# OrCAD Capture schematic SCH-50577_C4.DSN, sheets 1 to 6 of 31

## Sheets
1 31 Use Case Description: title: MIMXRT1180-EVK; rev: C4; company: NXP Semiconductors; note: SCH-50577, PDF: SPF-50577; note: 6501 William Cannon Drive West; note: Austin, TX 78735-8598
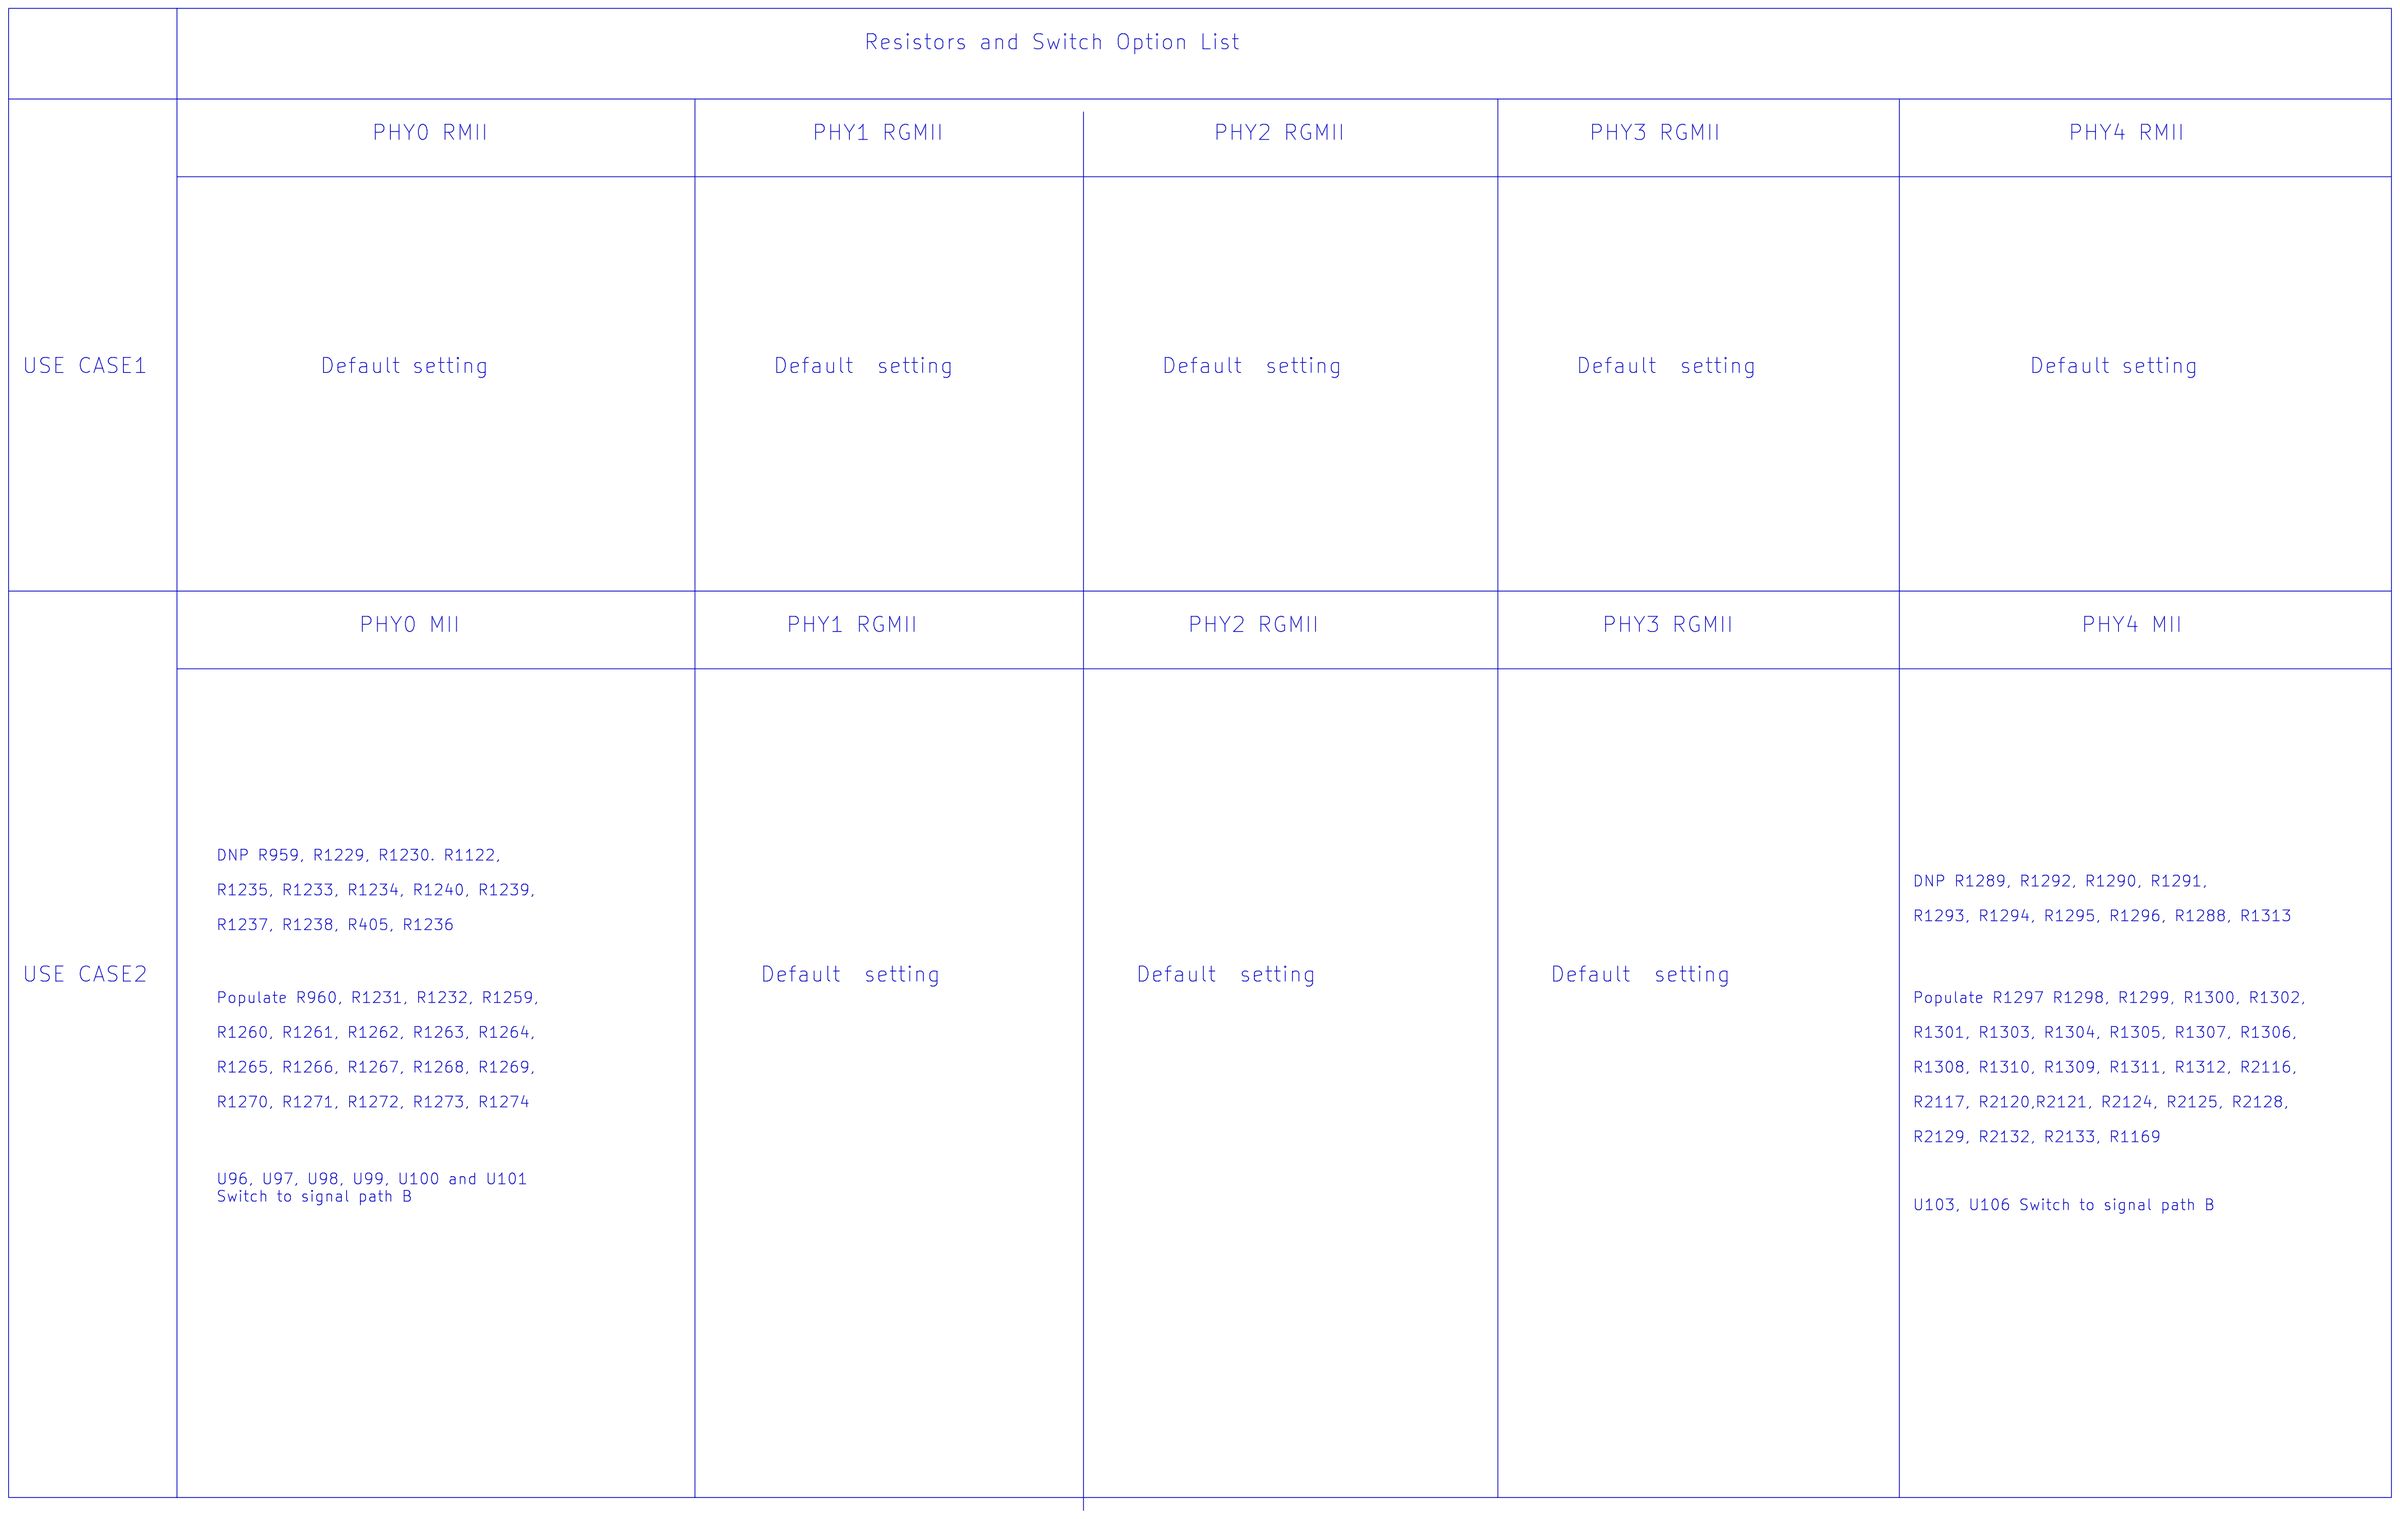
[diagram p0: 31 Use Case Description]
2 29 Serial to USB: size C
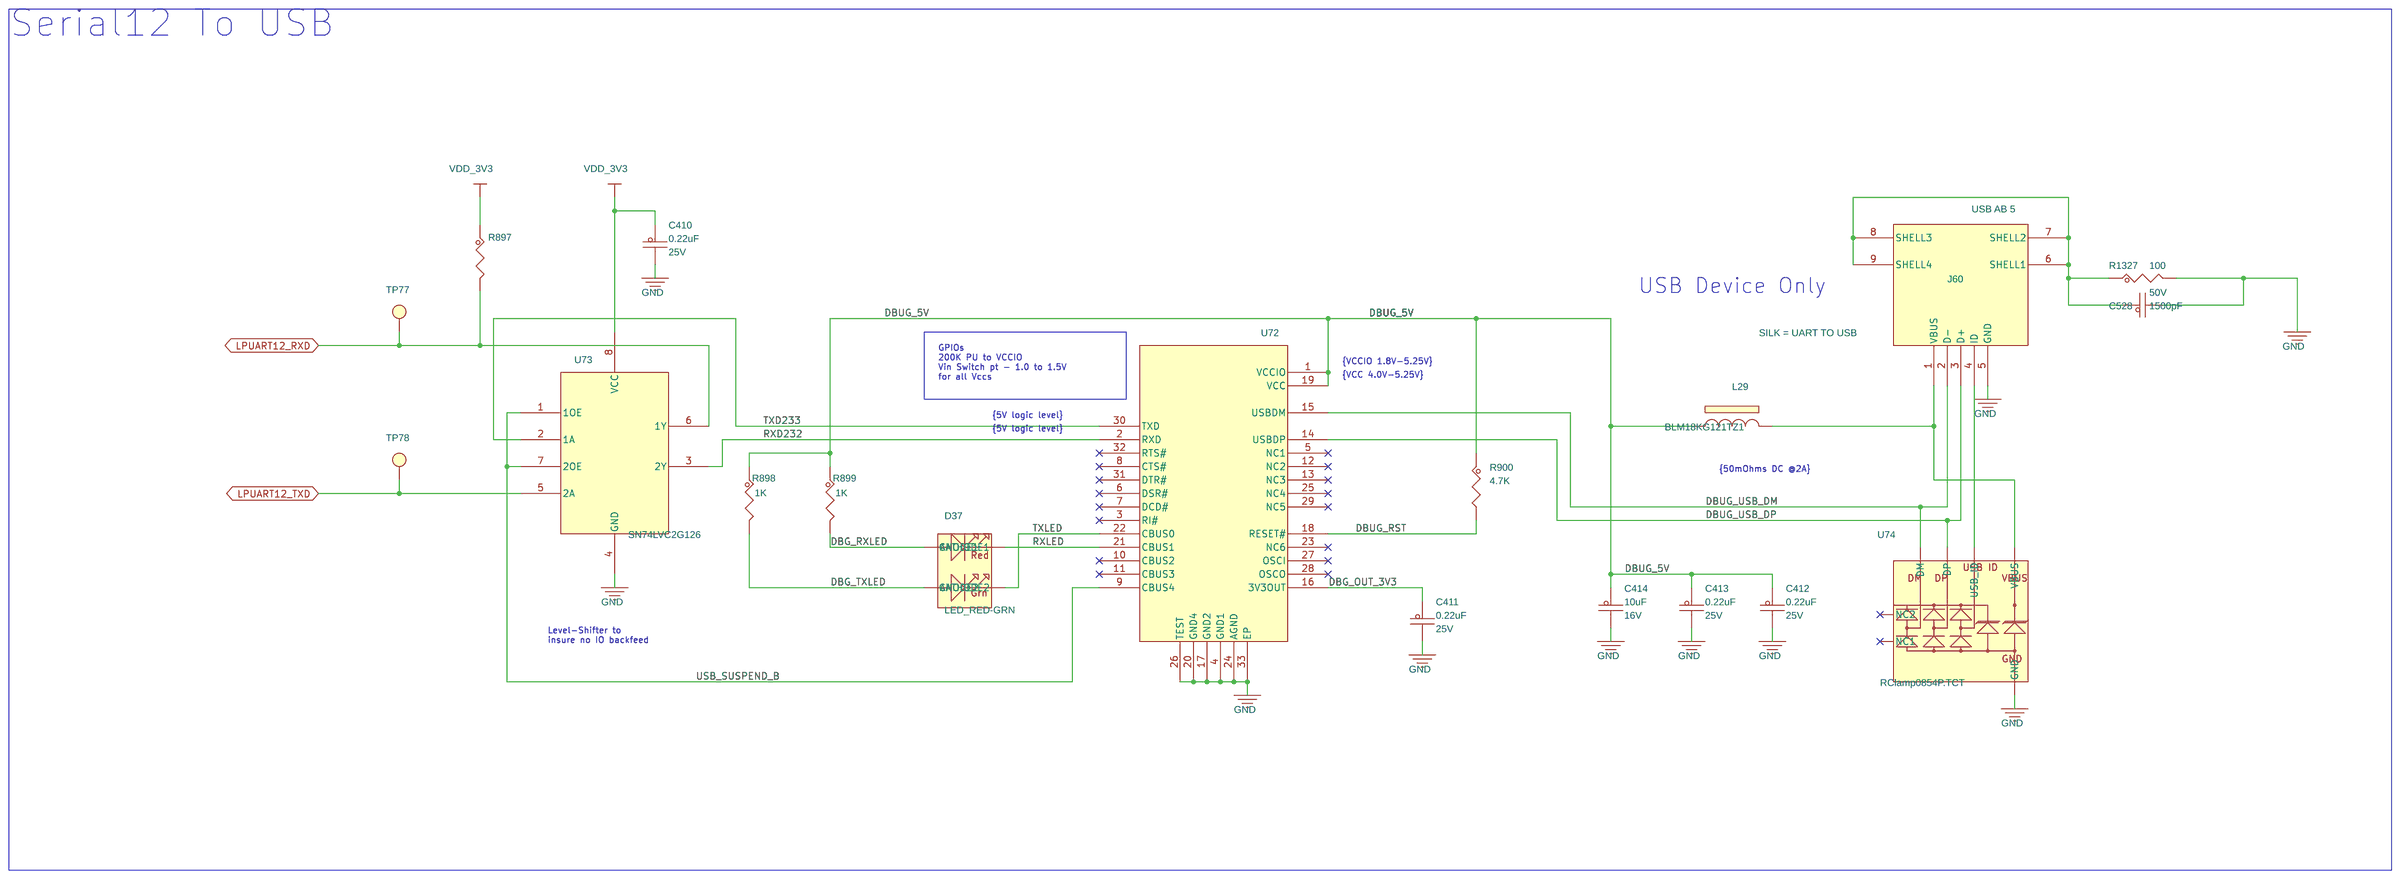
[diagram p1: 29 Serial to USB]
3 01 Cover
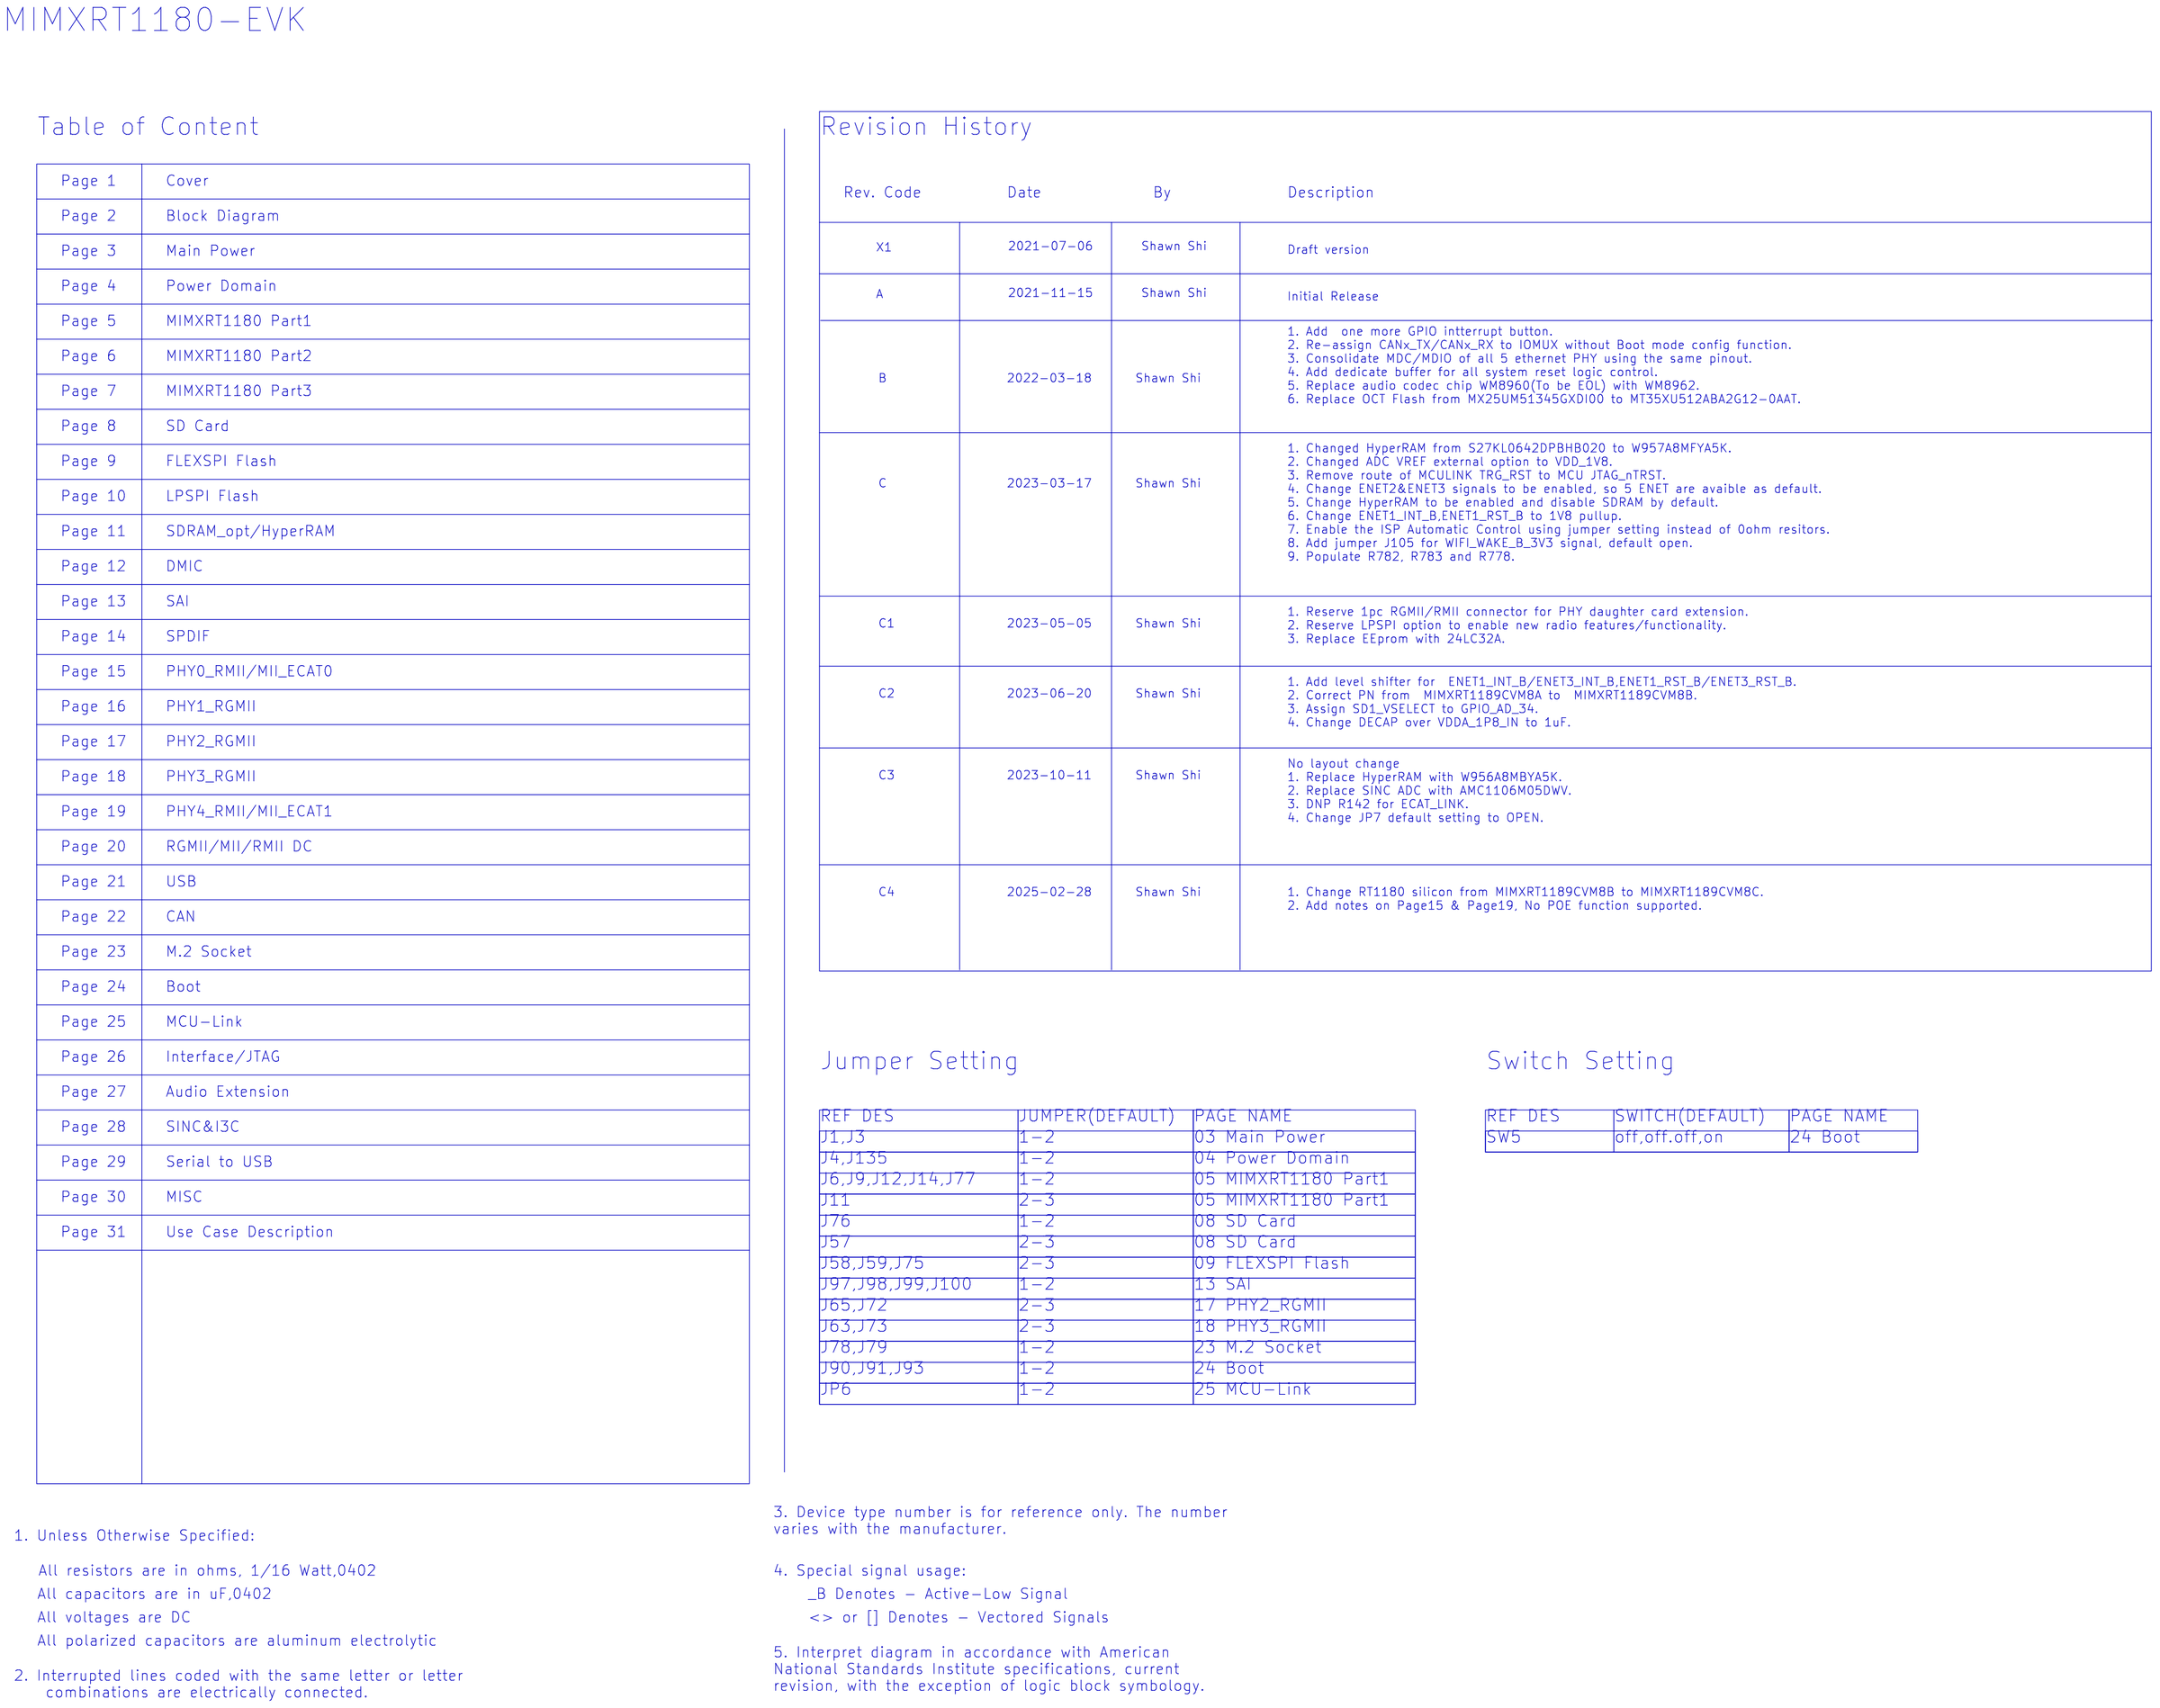
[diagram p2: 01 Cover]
4 02 Block Diagram
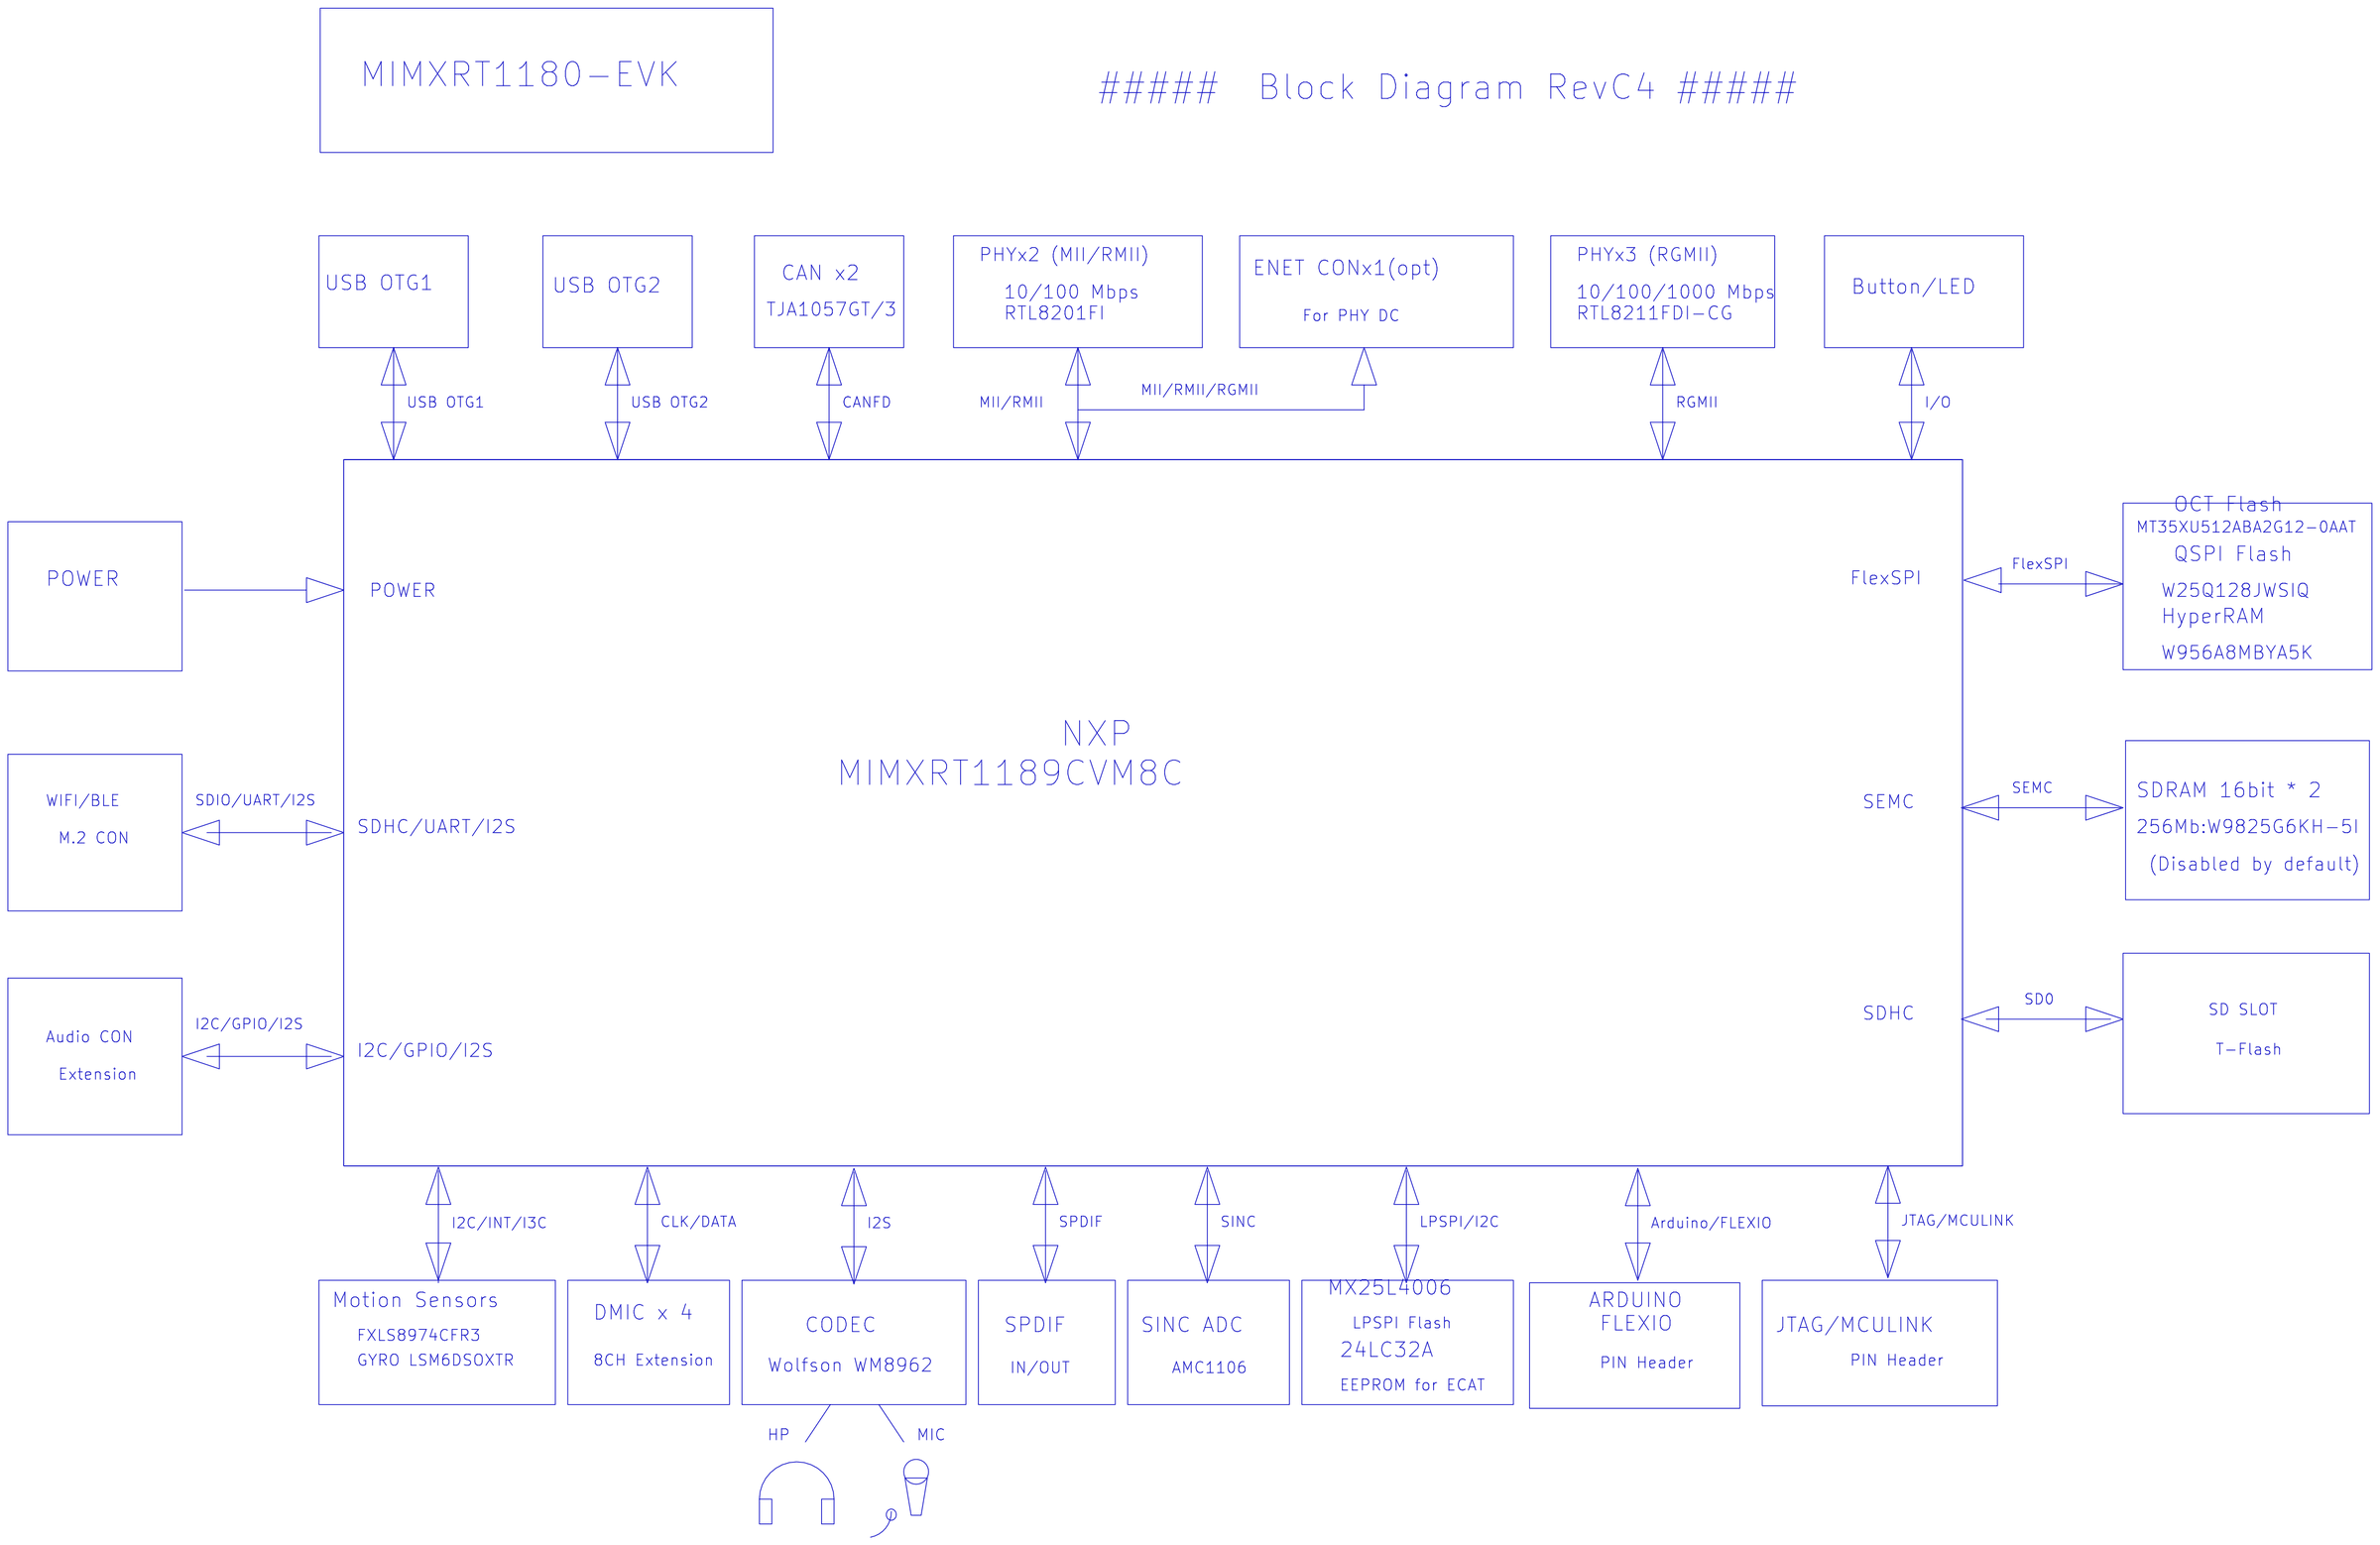
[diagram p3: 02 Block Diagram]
5 03 Main Power: size C
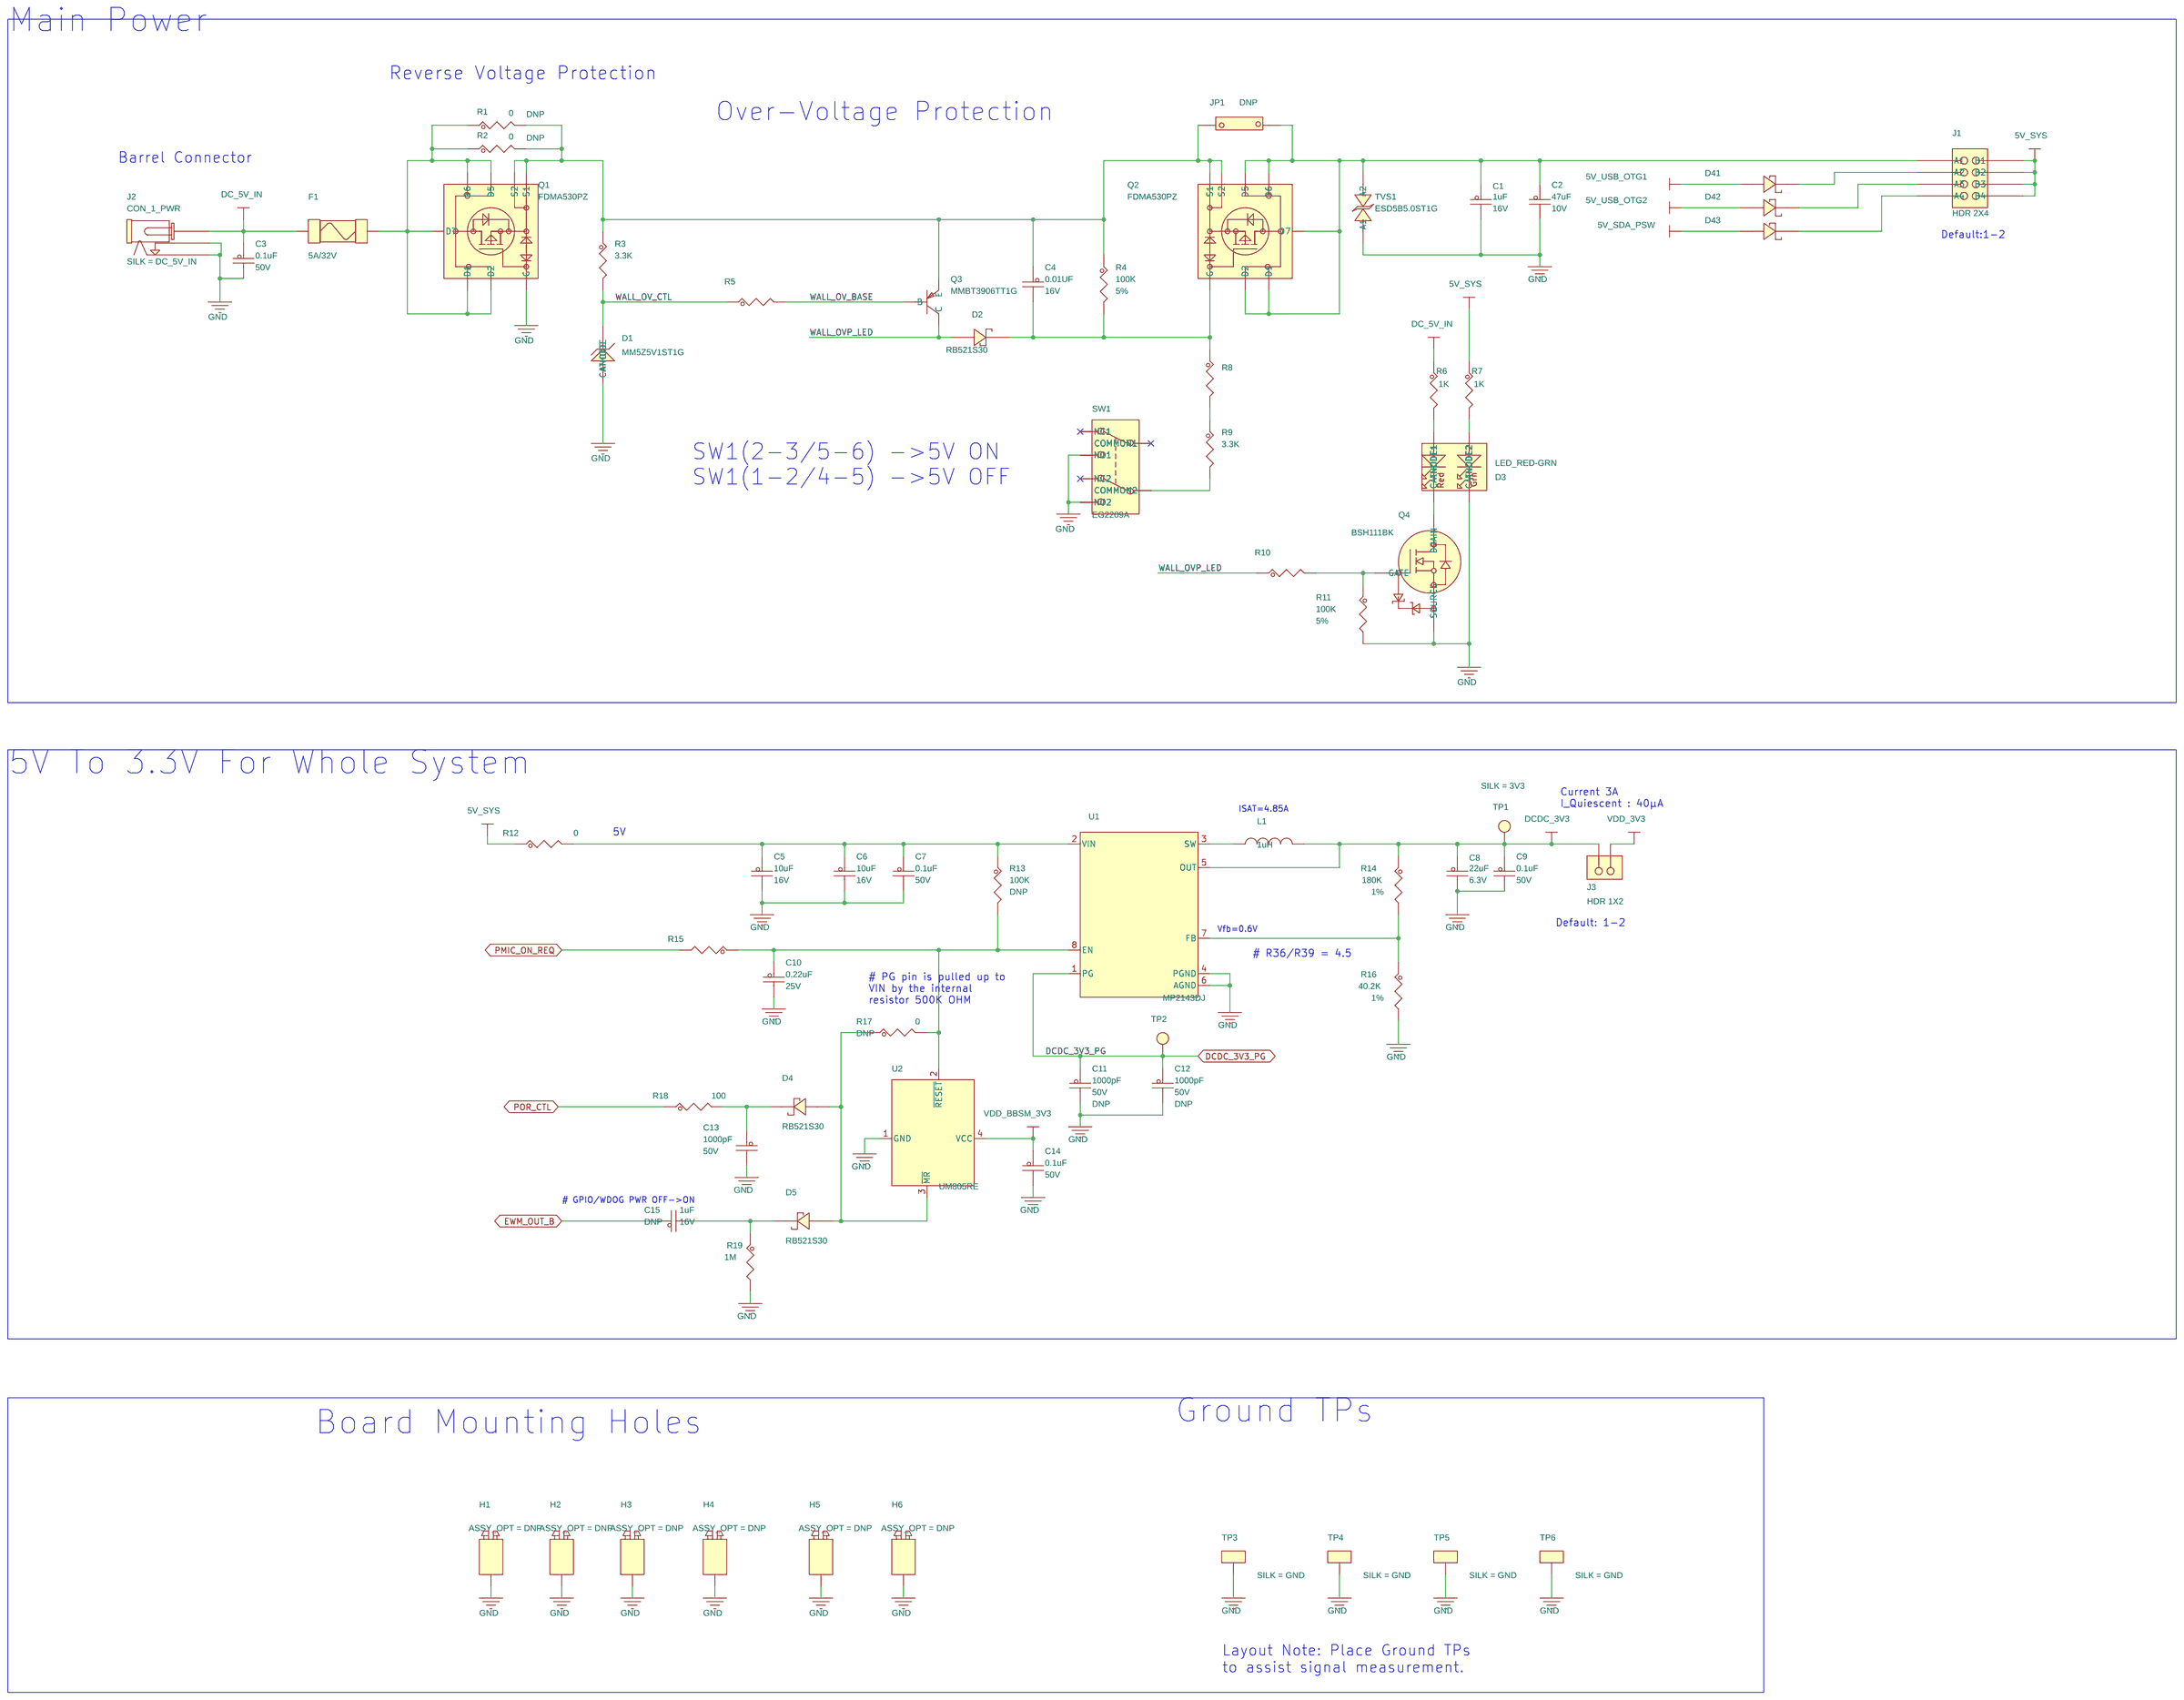
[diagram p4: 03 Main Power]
6 04 Power Domain: size C
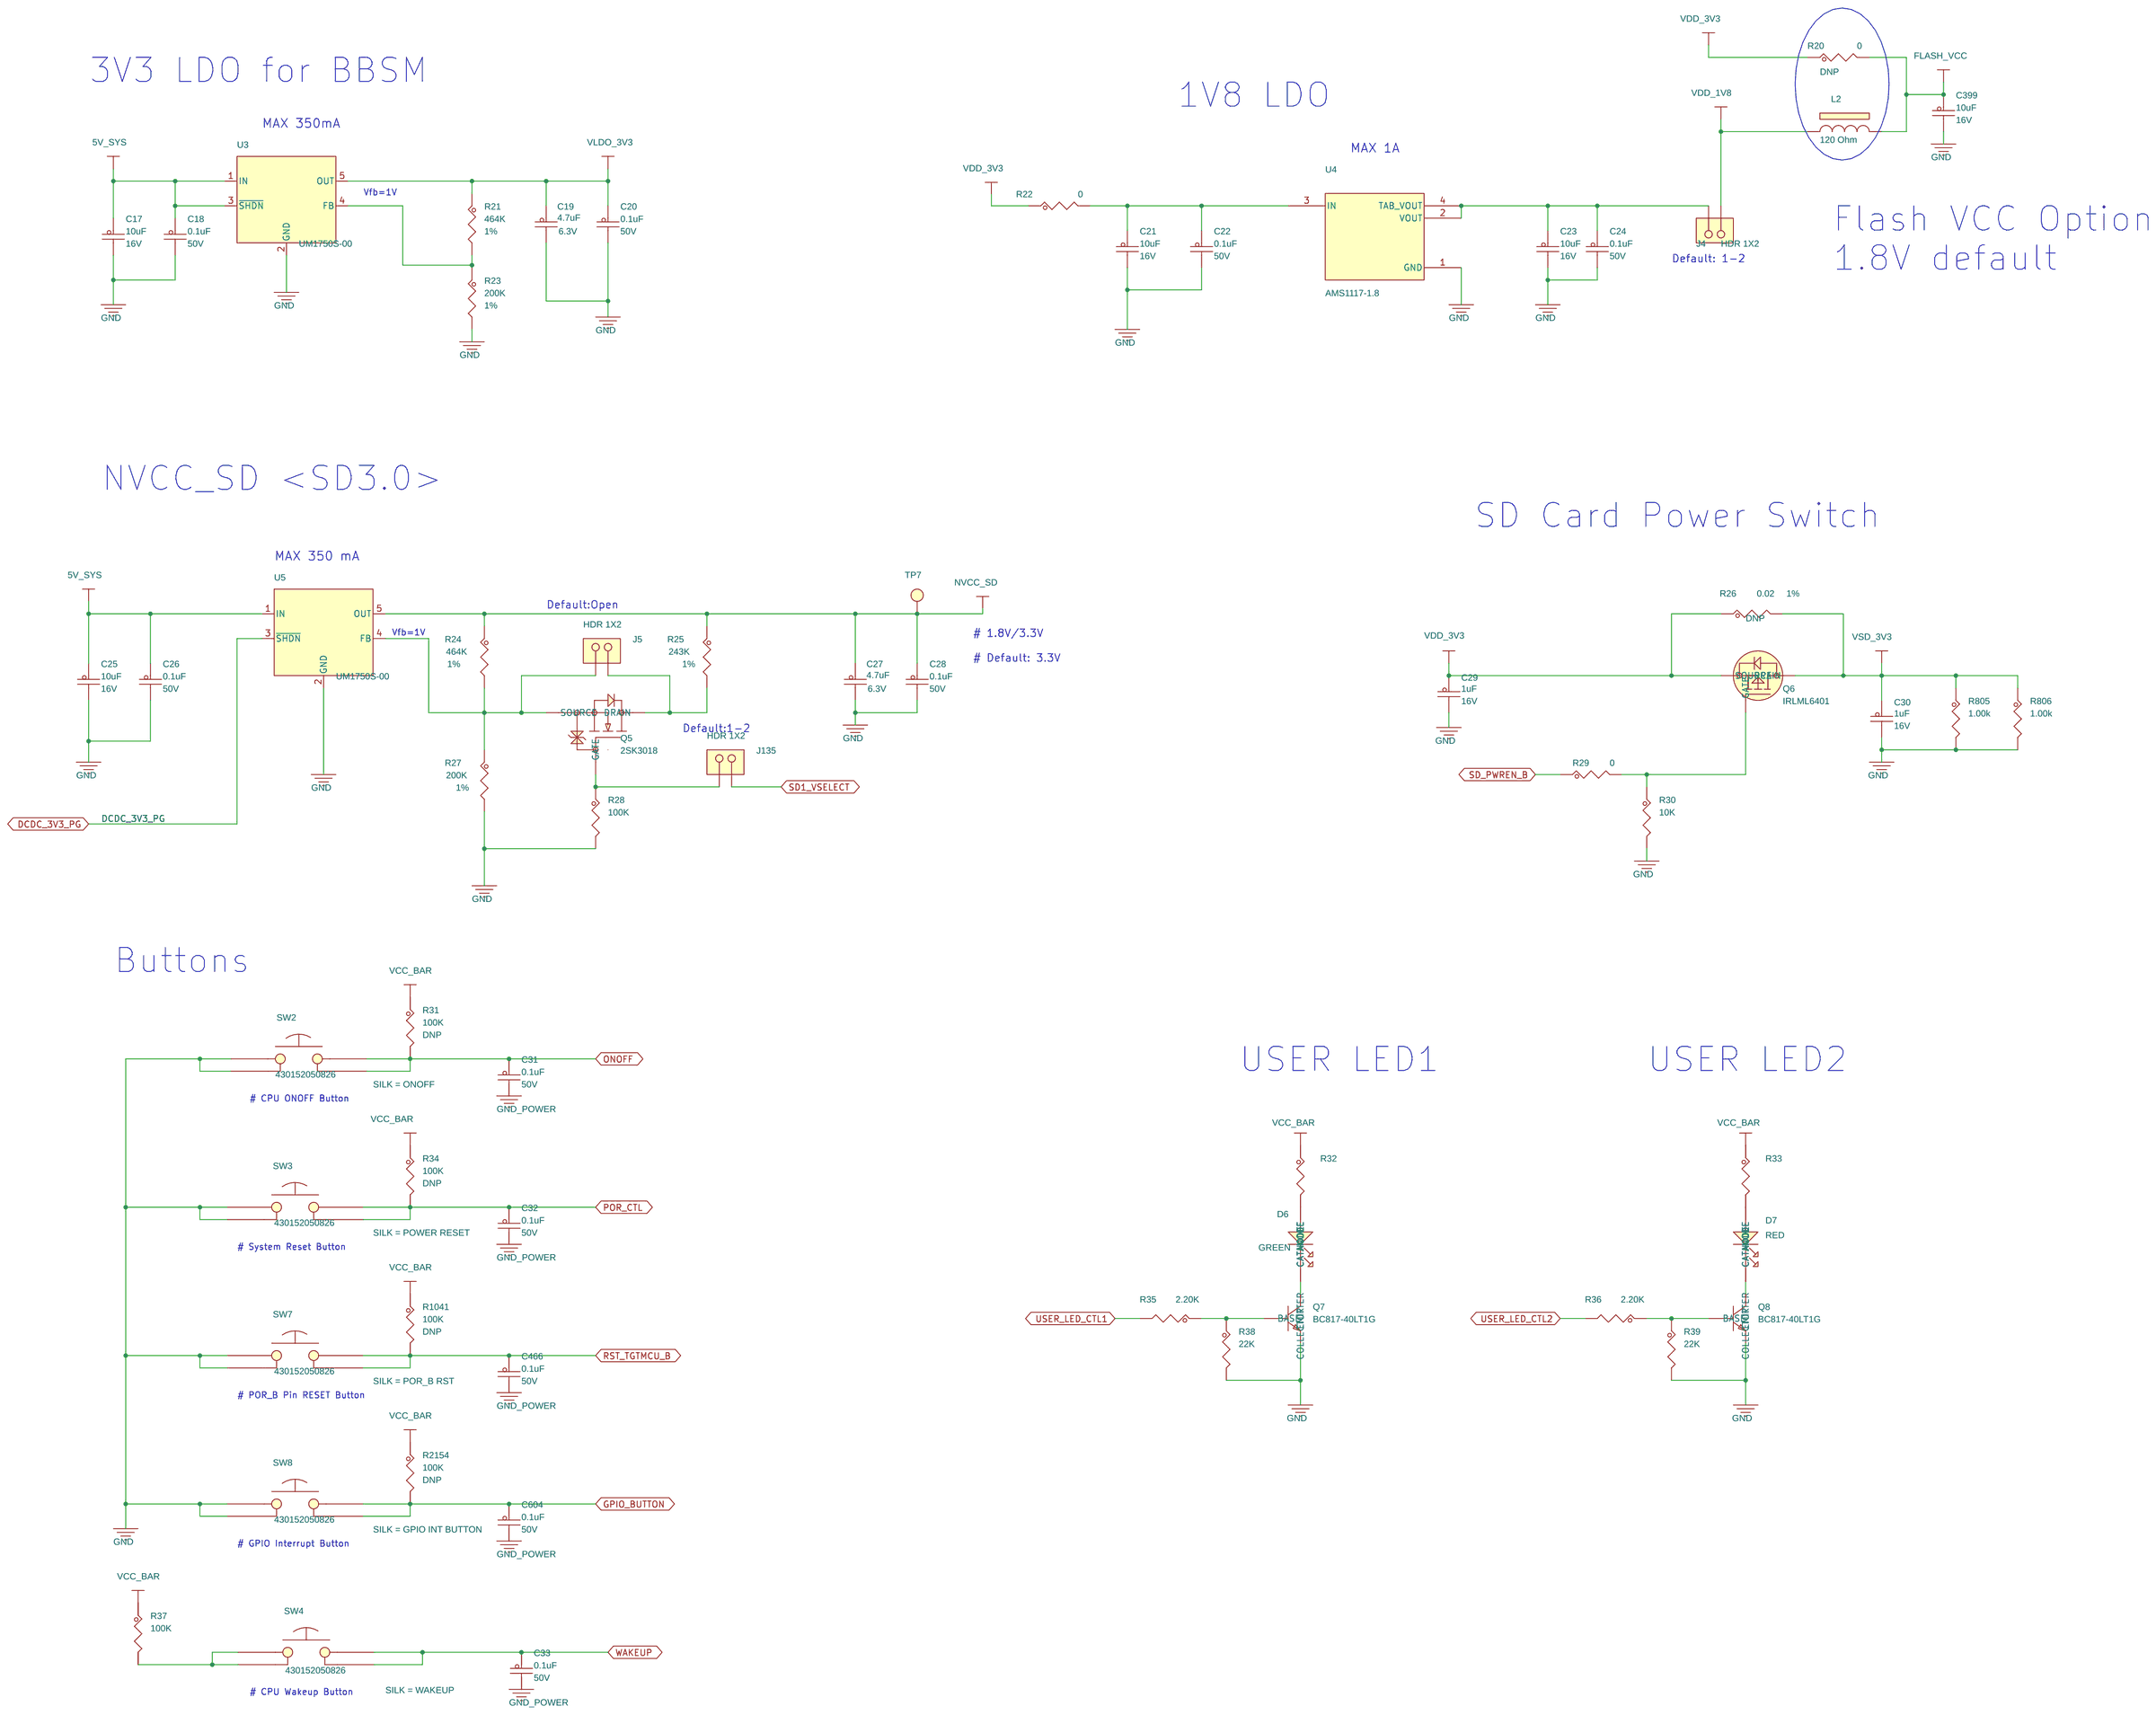
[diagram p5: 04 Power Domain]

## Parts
sheet 03 Main Power
C1  1uF  [0402_CC]
C2  47uF  [CC1206]
C3  0.1uF  [0402_CC]
C4  0.01UF  [0402_CC]
C5  10uF  [CC0603_OV]
C6  10uF  [CC0603_OV]
C7  0.1uF  [0402_CC]
C8  22uF  [CC0603_OV]
C9  0.1uF  [0402_CC]
C10  0.22uF  [0402_CC]
C11  1000pF  [0402_CC]
C12  1000pF  [0402_CC]
C13  1000pF  [0402_CC]
C14  0.1uF  [0402_CC]
C15  1uF  [0402_CC]
D1  MM5Z5V1ST1G  [sod_523_1p4]
D2  RB521S30  [SOD523]
D3  LED_RED-GRN  [LED_DUAL_3025MM_SM]
D4  RB521S30  [SOD523]
D5  RB521S30  [SOD523]
D41  MBR120VLSFT1G  [SOD-123]
D42  MBR120VLSFT1G  [SOD-123]
D43  MBR120VLSFT1G  [SOD-123]
F1  5A/32V  [fuse_3p4x1p8]
H1  .635" LONG  [spacer_139t]
H2  .635" LONG  [spacer_139t]
H3  .635" LONG  [spacer_139t]
H4  .635" LONG  [spacer_139t]
H5  .635" LONG  [spacer_139t]
H6  .635" LONG  [spacer_139t]
J1  HDR 2X4  [hdr2x4_2p54_th]
J2  CON_1_PWR  [con3_pwr_th]
J3  HDR 1X2  [HDR102]
JP1  SHORT_100mil  [100MIL_TH]
L1  1uH  [ind_4020]
Q1  FDMA530PZ  [MLP6_2X2MM_SLUG]
Q2  FDMA530PZ  [MLP6_2X2MM_SLUG]
Q3  MMBT3906TT1G  [sc_75]
Q4  BSH111BK  [SOT23_A]
R1  0  [0402_CC]
R2  0  [0402_CC]
R3  3.3K  [0402_CC]
R4  100K  [0402_CC]
R5  10K  [0402_CC]
R6  1K  [0402_CC]
R7  1K  [0402_CC]
R8  2.2K  [0402_CC]
R9  3.3K  [0402_CC]
R10  10K  [0402_CC]
R11  100K  [0402_CC]
R12  0  [RC0603_OV]
R13  100K  [0402_CC]
R14  180K  [0402_CC]
R15  10K  [0402_CC]
R16  40.2K  [0402_CC]
R17  0  [0402_CC]
R18  100  [0402_CC]
R19  1M  [0402_CC]
SW1  EG2209A  [sw6_dpdt_11x6mm]
TP1  TP_35MIL  [testpoint_35mil]
TP2  TP_35MIL  [testpoint_35mil]
TP3  5006  [tp_th_063]
TP4  5006  [tp_th_063]
TP5  5006  [tp_th_063]
TP6  5006  [tp_th_063]
TVS1  ESD5B5.0ST1G  [diode2_sod523]
U1  MP2143DJ  [tsot23_8_0p65_2x1]
U2  UM805RE  [sot_143]
sheet 04 Power Domain
C17  10uF  [CC0603_OV]
C18  0.1uF  [0402_CC]
C19  4.7uF  [cc0402_tol0p15]
C20  0.1uF  [0402_CC]
C21  10uF  [CC0603_OV]
C22  0.1uF  [0402_CC]
C23  10uF  [CC0603_OV]
C24  0.1uF  [0402_CC]
C25  10uF  [CC0603_OV]
C26  0.1uF  [0402_CC]
C27  4.7uF  [cc0402_tol0p15]
C28  0.1uF  [0402_CC]
C29  1uF  [0402_CC]
C30  1uF  [0402_CC]
C31  0.1uF  [0402_CC]
C32  0.1uF  [0402_CC]
C33  0.1uF  [0402_CC]
C399  10uF  [CC0603_OV]
C466  0.1uF  [0402_CC]
C604  0.1uF  [0402_CC]
D6  GREEN  [LED_0603]
D7  RED  [LED_0603]
J4  HDR 1X2  [HDR102]
J5  HDR 1X2  [HDR102]
J135  HDR 1X2  [HDR102]
L2  120 Ohm  [0402_CC]
Q5  2SK3018  [SOT323_3]
Q6  IRLML6401  [sot-23]
Q7  BC817-40LT1G  [SOT23]
Q8  BC817-40LT1G  [SOT23]
R20  0  [0402_CC]
R21  464K  [0402_CC]
R22  0  [0402_CC]
R23  200K  [0402_CC]
R24  464K  [0402_CC]
R25  243K  [0402_CC]
R26  0.02  [RC0603_OV]
R27  200K  [0402_CC]
R28  100K  [0402_CC]
R29  0  [0402_CC]
R30  10K  [0402_CC]
R31  100K  [0402_CC]
R32  220  [RC0603_OV]
R33  220  [RC0603_OV]
R34  100K  [0402_CC]
R35  2.20K  [RC0603_OV]
R36  2.20K  [RC0603_OV]
R37  100K  [0402_CC]
R38  22K  [0402_CC]
R39  22K  [0402_CC]
R805  1.00k  [0402_CC]
R806  1.00k  [0402_CC]
R1041  100K  [0402_CC]
R2154  100K  [0402_CC]
SW2  430152050826  [sw4_pb_6p2sq_sm]
SW3  430152050826  [sw4_pb_6p2sq_sm]
SW4  430152050826  [sw4_pb_6p2sq_sm]
SW7  430152050826  [sw4_pb_6p2sq_sm]
SW8  430152050826  [sw4_pb_6p2sq_sm]
TP7  TP_35MIL  [testpoint_35mil]
U3  UM1750S-00  [sot23-5_a]
U4  AMS1117-1.8  [sot223]
U5  UM1750S-00  [sot23-5_a]
sheet 29 Serial to USB
C410  0.22uF  [0402_CC]
C411  0.22uF  [0402_CC]
C412  0.22uF  [0402_CC]
C413  0.22uF  [0402_CC]
C414  10uF  [CC0603_OV]
C528  1500pF  [0402_CC]
D37  LED_RED-GRN  [LED_DUAL_3025MM_SM]
J60  USB AB 5  [con9_microAB_usb_shell_th]
L29  BLM18KG121TZ1  [IND_0603]
R897  10K  [0402_CC]
R898  1K  [0402_CC]
R899  1K  [0402_CC]
R900  4.7K  [0402_CC]
R1327  100  [0402_CC]
TP77  TP_35MIL  [testpoint_35mil]
TP78  TP_35MIL  [testpoint_35mil]
U72  FT232RQ  [qfn32_mc1320x]
U73  SN74LVC2G126  [SSOP8]
U74  RClamp0854P.TCT  [slp1616p6]

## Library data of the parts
C1 C29 C30 = CAP_NP: CAP CER 1.0uF 16V 10% X6S 0402; AGILE_PN: 150-80262; CAD_APPROVED: Yes; FPLIST: CC0402_25,CC0402_HD,0402_CC,capc0402_l; HEIGHT: 0.55MM; MFG_NAME01: MURATA; MFG_PN01: GRM155C81C105KE11D; ROHS: Yes; Temp Range: -55°C to +105°C; Tolerance: 10%; VOLTAGE: 16V
C2 = CAP_NP: CAP CER 47uF 10V 20% X6S 1206; 3D_Mechanical_Footprint_File: ftp://fcl.am.freescale.net/ALLEGRO/step/1206_CC.STEP; AGILE_PN: 150-81387; CAD_APPROVED: Yes; FPLIST: CC1206,1206_CC; HEIGHT: 1.8MM; MFG_NAME01: TDK; MFG_PN01: C3216X6S1A476M160AC; Package Size: 1206; Package Type: SMT; ROHS: Yes; Rated Voltage: 10V; Temp Range: -55C to 105 C; Tolerance: 20%; VOLTAGE: 10V
C3 C7 C9 C14 C18 C20 C22 C24 C26 C28 C31-C33 C466 C604 = CAP_NP: CAP CER 0.1uF 50V 10% X7R AEC-Q200 0402; AGILE_PN: 150-79461; CAD_APPROVED: Yes; FPLIST: CC0402_25,CC0402_HD,0402_CC,CC0402_18,capc0402_l; HEIGHT: 0.55MM; MFG_NAME01: MURATA; MFG_PN01: GCM155R71H104KE02D; Package Size: 0402; ROHS: Yes; Tolerance: 10%; VOLTAGE: 50V
C4 = CAP_NP: CAP CER 0.01UF 16V 20% X7R 0402; AGILE_PN: 150-30082; CAD_APPROVED: Yes; FPLIST: CC0402_25,CC0402_HD,0402_CC; HEIGHT: 0.56MM; MFG_NAME01: AVX; MFG_PN01: 0402YC103MAT2A; Package Size: 0402; ROHS: Yes; TOL: 20%; Tolerance: 20%; VOLTAGE: 16V
C5 C6 C17 C21 C23 C25 C399 C414 = CAP_NP: CAP CER 10uF 16V 20% X6S AEC-Q200 0603; AGILE_PN: 150-80530; CAD_APPROVED: Yes; FPLIST: CC0603_OV,CC0603,0603_CC_NSP; HEIGHT: 1MM; MFG_NAME01: MURATA; MFG_PN01: GRT188C81C106ME13D; Package Size: 0603; ROHS: Yes; Temp Range: -55°C to 105°C; Tolerance: 10%; VOLTAGE: 16V
C8 = CAP_NP: CAP CER 22uF 6.3V 20% X6S 0603; AGILE_PN: 150-79717; CAD_APPROVED: Yes; FPLIST: CC0603_OV,CC0603,0603_CC_NSP; HEIGHT: 1MM; MFG_NAME01: MURATA; MFG_PN01: GRM188C80J226ME15D; Package Size: 0603; Package Type: 180mm ReelPAPER W8P4; ROHS: Yes; Tolerance: 20%; VOLTAGE: 6.3V
C10 C410-C413 = CAP_NP: CAP CER 0.22uF 25V 10% X6S AEC-Q200 0402; AGILE_PN: 150-79689; CAD_APPROVED: Yes; FPLIST: CC0402_25,CC0402_HD,0402_CC,capc0402_l; HEIGHT: 0.55MM; MFG_NAME01: MURATA; MFG_PN01: GRT155C81E224KE01; Package Size: 0402; ROHS: Yes; Tolerance: 10%; VOLTAGE: 25V
C11 C12 = CAP_NP: CAP CER 1000PF 50V 5% C0G 0402; AGILE_PN: 150-76334; ASSY_OPT: DNP; CAD_APPROVED: Yes; FPLIST: CC0402_25,CC0402_HD,0402_CC; HEIGHT: 0.55MM; MFG_NAME01: MURATA; MFG_PN01: GRM1555C1H102JA01D; Package Size: 0402; Package Type: 180mm Paper Tape; ROHS: Yes; Tolerance: 5%; VOLTAGE: 50V
C13 = CAP_NP: CAP CER 1000PF 50V 5% C0G 0402; AGILE_PN: 150-76334; CAD_APPROVED: Yes; FPLIST: CC0402_25,CC0402_HD,0402_CC; HEIGHT: 0.55MM; MFG_NAME01: MURATA; MFG_PN01: GRM1555C1H102JA01D; Package Size: 0402; Package Type: 180mm Paper Tape; ROHS: Yes; Tolerance: 5%; VOLTAGE: 50V
C15 = CAP_NP: CAP CER 1.0uF 16V 10% X6S 0402; AGILE_PN: 150-80262; ASSY_OPT: DNP; CAD_APPROVED: Yes; FPLIST: CC0402_25,CC0402_HD,0402_CC,capc0402_l; HEIGHT: 0.55MM; MFG_NAME01: MURATA; MFG_PN01: GRM155C81C105KE11D; ROHS: Yes; Temp Range: -55°C to +105°C; Tolerance: 10%; VOLTAGE: 16V
D1 = ZDIODE: DIODE ZNR -- 0.2W 5.1V AEC-Q101 SOD523; AGILE_PN: 480-77217; CAD_APPROVED: Yes; HEIGHT: 0.7MM; MFG_NAME01: ON SEMICONDUCTOR; ROHS: Yes
D2 D4 D5 = DIODE_SCHTKY: DIODE SCH RECT 200MA 30V AEC-Q101 SOD-523; AGILE_PN: 480-79672; CAD_APPROVED: Yes; HEIGHT: 0.65MM; MFG_NAME01: NEXPERIA; MFG_PN01: RB521S30,115; ROHS: Yes; VOLTAGE: 30V
D3 = LED_DUAL_SEP_RG: LED RED GRN DUAL 30/25MA SMT; AGILE_PN: 370-75097; CAD_APPROVED: Yes; HEIGHT: 1.1MM; MFG_NAME01: KINGBRIGHT; MFG_PN01: APB3025ESGC-F01; ROHS: Yes
D41-D43 = DIODE_SCHTKY: DIODE SCH RECT 1A 20V SMT; AGILE_PN: 480-75997; CAD_APPROVED: Yes; HEIGHT: 1MM; MFG_NAME01: ON SEMICONDUCTOR; ROHS: Yes; VOLTAGE: 20V
F1 = FUSE: FUSE FAST 5A 32V SMT; AGILE_PN: 510-77398; CAD_APPROVED: Yes; HEIGHT: 1.09MM; MFG_NAME01: COOPER BUSSMANN; MFG_PN01: 3216FF5-R; ROHS: Yes
H1-H6 = SPACER: FASTENER, STANDOFF 4.5MMX3.53XM3.0X0.5 ROUND THR .635"L BRASS; AGILE_PN: 280-76498; ASSY_OPT: DNP; CAD_APPROVED: Yes; HEIGHT: 16.13MM; MFG_NAME01: UNICORP; MFG_PN01: MSS251-R-1-A-16; ROHS: Yes
J1 = CONN_HDR_4X2: HDR 2X4 TH 100MIL CTR 344H AU 118L; 3D_Mechanical_Footprint_File: ftp://fcl.am.freescale.net/ALLEGRO/step/hdr2x4_2p54_th.STEP; AGILE_PN: 210-81937; CAD_APPROVED: Yes; HEIGHT: 8.74MM; Jumper(Default): 1-2; MFG_NAME01: WURTH ELEKTRONIK EISOS GMBH & CO. KG (ELECTRONIC & ELECTROMEHANICAL COMP); MFG_PN01: 61300821121; Package Type: TH; ROHS: Yes; Temp Range: -40 to 105C
J2 = PHONEJACK-3: CON 1 PWR PLUG RA TH 2.5A 20V -- 441H SN/NI; AGILE_PN: 210-80780; CAD_APPROVED: Yes; HEIGHT: 11.2MM; MFG_NAME01: SHENZHEN ATOM TECHNOLOGY CO.,LTD; MFG_PN01: DC060024202; Package Type: TH; ROHS: Yes; SILK: DC_5V_IN
J3 J4 = CONN_HDR_2X1: HDR 1X2 TH 100MIL SP 339H AU 98L; AGILE_PN: 210-81490; CAD_APPROVED: Yes; HEIGHT: 8.59MM; Jumper(Default): 1-2; MFG_NAME01: ANYTRONIC CORPORATION LIMITED; MFG_PN01: 0901S0202011N9T-31RF; ROHS: Yes; Temp Range: -55°C to +105°C; Temp_Range: -55°C to +105°C
JP1 = JUMPER1x2: CON 2 JUMPER MALE 2.54MM SP 157H AU; 3D_Mechanical_Footprint_File: ftp://fcl.am.freescale.net/ALLEGRO/step/100mil_th.STEP; AGILE_PN: 210-30004; ASSY_OPT: DNP; CAD_APPROVED: Yes; HEIGHT: 4MM; MFG_NAME01: PRECI-DIP CONNECTION TECHNOLOGY; MFG_PN01: 999-11-110-10; ROHS: Yes
L1 = IND: IND PWR 1UH@100KHZ 2.6A 30% SMT; AGILE_PN: 180-77797; CAD_APPROVED: Yes; HEIGHT: 2.2MM; MFG_NAME01: SHENZHEN SUNLORD ELECTRONICS CO., LTD; MFG_PN01: SWPA4020S1R0NT; PART_TYPE: INDUCTOR\POWER; Package Size: 4020; ROHS: Yes; TOL: 30%; Tolerance: 30%
Q1 Q2 = FDMA530PZ: TRAN PMOS PWR 30V 6.8A; AGILE_PN: 480-77039; CAD_APPROVED: Yes; HEIGHT: 0.8MM; MFG_NAME01: FAIRCHILD; ROHS: Yes
Q3 = PNP: TRAN PNP GEN AMP 200MA 40V AEC-Q101 SC75; AGILE_PN: 480-78465; CAD_APPROVED: Yes; HEIGHT: 0.9 MM; MFG_NAME01: ON SEMICONDUCTOR; ROHS: Yes
Q4 = NMOS_2N7002BKW_3P: TRAN NMOS SW FET 55V 210mA SOT23; AGILE_PN: 480-79704; CAD_APPROVED: Yes; HEIGHT: 1.1MM; MFG_NAME01: NEXPERIA; MFG_PN01: BSH111BKR; ROHS: Yes
R1 R2 R17 = RES: RES MF ZERO OHM 1/16W 5% 0402; AGILE_PN: 470-75394; ASSY_OPT: DNP; CAD_APPROVED: Yes; FPLIST: RC0402_25,RC0402_HD,RC0402_X2,0402_CC; HEIGHT: 0.45 MM; MFG_NAME01: ROHM; MFG_PN01: MCR01MZPJ000; ROHS: Yes; Tolerance: 5%; VOLTAGE: 1/16W
R3 R9 = RES: RES MF 3.3K 1/16W 5% 0402; AGILE_PN: 470-76064; CAD_APPROVED: Yes; FPLIST: RC0402_25,RC0402_HD,0402_CC; HEIGHT: 0.40 MM; MFG_NAME01: YAGEO AMERICA; MFG_PN01: RC0402JR-073K3L; ROHS: Yes; TOL: 5%; Tolerance: 5%; VOLTAGE: 1/16W
R4 R11 = RES: RES MF 100K 1/16W 5% 0402; AGILE_PN: 470-75597; CAD_APPROVED: Yes; FPLIST: RC0402_25,RC0402_HD,0402_CC; HEIGHT: 0.40 MM; MFG_NAME01: VENKEL COMPANY; MFG_PN01: CR0402-16W-104JT; ROHS: Yes; TOL: 5%; Temp Range: -55C to +155C; Temp_Range: -55C to +155C; Tolerance: 5%; VOLTAGE: 50V
R5 R10 R897 = RES: RES MF 10K 1/16W 5% 0402; AGILE_PN: 470-75557; CAD_APPROVED: Yes; FPLIST: RC0402_25,RC0402_HD,0402_CC; HEIGHT: 0.4 MM; MFG_NAME01: VISHAY INTERTECHNOLOGY; MFG_PN01: CRCW040210K0JNED; ROHS: Yes; TOL: 5%; Tolerance: 5%
R6 R7 R898 R899 = RES: RES MF 1.0K 1/16W 5% 0402; AGILE_PN: 470-75555; CAD_APPROVED: Yes; FPLIST: RC0402_25,RC0402_HD,RC0402_X2,0402_CC; HEIGHT: 0.41mm; MFG_NAME01: VISHAY INTERTECHNOLOGY; MFG_PN01: CRCW04021K00JNED; ROHS: Yes; Tolerance: 5%
R8 = RES: RES MF 2.2K 1/16W 5% 0402; AGILE_PN: 470-76602; CAD_APPROVED: Yes; FPLIST: RC0402_25,RC0402_HD,0402_CC; HEIGHT: 0.4 MM; MFG_NAME01: YAGEO AMERICA; MFG_PN01: RC0402JR-072K2L; ROHS: Yes; TOL: 5%; Tolerance: 5%
R12 = RES: RES MF ZERO OHM 1/10W -- 0603; AGILE_PN: 470-80866; CAD_APPROVED: Yes; FPLIST: RC0603_OV,RC0603,R603-X2,0603_CC; HEIGHT: 0.6MM; MFG_NAME01: YAGEO AMERICA; MFG_PN01: RC0603FR-070RL; ROHS: Yes; SIGNAL_MODEL: DEFAULT_RESISTOR_0.001OHM_2_1; Temp Range: –55 °C to +155 °C; Temp_Range: –55 °C to +155 °C
R13 R31 R34 R1041 R2154 = RES: RES MF 100K 1/16W 5% 0402; AGILE_PN: 470-75597; ASSY_OPT: DNP; CAD_APPROVED: Yes; FPLIST: RC0402_25,RC0402_HD,0402_CC; HEIGHT: 0.40 MM; MFG_NAME01: VENKEL COMPANY; MFG_PN01: CR0402-16W-104JT; ROHS: Yes; Temp Range: -55C to +155C; Temp_Range: -55C to +155C; Tolerance: 5%; VOLTAGE: 50V
R14 = RES: RES MF 180K 1/10W 1% AEC-Q200 0402; AGILE_PN: 470-31088; CAD_APPROVED: Yes; FPLIST: RC0402_25,RC0402_HD,0402_CC; HEIGHT: 0.40 MM; MFG_NAME01: KOA SPEER; MFG_PN01: RK73H1ETTP1803F; ROHS: Yes; Temp Range: -55C to +155C; Temp_Range: -55C to +155C; Tolerance: 1%
R15 R30 = RES: RES MF 10K 1/16W 5% 0402; AGILE_PN: 470-75557; CAD_APPROVED: Yes; FPLIST: RC0402_25,RC0402_HD,0402_CC; HEIGHT: 0.4 MM; MFG_NAME01: VISHAY INTERTECHNOLOGY; MFG_PN01: CRCW040210K0JNED; ROHS: Yes; Tolerance: 5%
R16 = RES: RES MF 40.2K  1/16W 1% 0402; AGILE_PN: 470-31015; CAD_APPROVED: Yes; FPLIST: RC0402_25,RC0402_HD,0402_CC; HEIGHT: 0.40 MM; MFG_NAME01: YAGEO AMERICA; MFG_PN01: RC0402FR-0740K2L; ROHS: Yes; Temp Range: -55C to +155C; Temp_Range: -55C to +155C; Tolerance: 1%
R18 = RES: RES MF 100 OHM 1/16W 1% 0402; AGILE_PN: 470-30454; CAD_APPROVED: Yes; FPLIST: RC0402_25,RC0402_HD,0402_CC; HEIGHT: 0.4 MM; MFG_NAME01: THYE MING TECH CO LTD; MFG_PN01: CR-02FL6--100R; ROHS: Yes; Tolerance: 1%; VOLTAGE: 50V
R19 = RES: RES MF 1M 1/10W 5% AEC-Q200 0402; AGILE_PN: 470-79978; CAD_APPROVED: Yes; FPLIST: RC0402_25,RC0402_HD,0402_CC; HEIGHT: 0.4MM; MFG_NAME01: KOA SPEER; MFG_PN01: RK73B1ETTP105J; ROHS: Yes; Temp Range: -55&#8451; to 155&#8451;; Temp_Range: -55&#8451; to 155&#8451;; Tolerance: 5%; VOLTAGE: 50V
SW1 = SW_DPDT_3: SW DPDT SLD 0.1A 12V L=4 TH; AGILE_PN: 510-77598; CAD_APPROVED: Yes; HEIGHT: 9.5MM; MFG_NAME01: E SWITCH; ROHS: Yes
TP1 = T_POINT_R: TEST POINT PAD .035 SMT, no part to order; AGILE_PN: 510-75618; CAD_APPROVED: Yes; HEIGHT: 0.1MM; ROHS: Yes; SILK: 3V3
TP2 TP7 TP77 TP78 = T_POINT_R: TEST POINT PAD .035 SMT, no part to order; AGILE_PN: 510-75618; CAD_APPROVED: Yes; HEIGHT: 0.1MM; ROHS: Yes
TP3-TP6 = TEST_POINT: TEST POINT BLK 70X220 MIL TH; AGILE_PN: 210-30155; CAD_APPROVED: Yes; HEIGHT: 5.6MM; MFG_NAME01: Keystone Electronics; ROHS: Yes; SILK: GND
TVS1 = DIODE_TVS_BIDIR: DIODE SUPPRESSOR 16A@30NS 5V@1UA SOD-523; AGILE_PN: 480-76937; CAD_APPROVED: Yes; HEIGHT: 0.7MM; MFG_NAME01: on semiconductor; ROHS: Yes
U1 = MP2144GJ_TSOT23_8P: IC SYNC STEP-DOWN SW 1.2MHZ 0.6V 3A 2.5-5.5V TSOT23-8; AGILE_PN: 315-81886; CAD_APPROVED: Yes; HEIGHT: 1MM; MFG_NAME01: MONOLITHIC POWER SYSTEMS; ROHS: Yes; Temp Range: -40C to 125C; Temp_Range: -40C to 125C; VOLTAGE: 2.5-5.5V
U2 = UM805_4P: IC VOLT MONITOR 2.63V VTH RST 1-5.5V SOT143; AGILE_PN: 315-80564; CAD_APPROVED: Yes; HEIGHT: 1.22MM; MFG_NAME01: UNION SEMICONDUCTOR, INC; ROHS: Yes; VOLTAGE: 1-5.5V
C19 C27 = CAP_NP: CAP CER 4.7uF 6.3V 20% X6S 0402; AGILE_PN: 150-81296; CAD_APPROVED: Yes; FPLIST: cc0402_tol0p15,cc0402_tol0p15_ov,cc0402_25_tol0p2,0402_cc_nsp; HEIGHT: 0.65MM; MFG_NAME01: MURATA; MFG_PN01: GRM155C80J475MEAA; Package Size: 0402 (1005 Metric); Package Type: SMD/SMT; ROHS: Yes; Rated Voltage: 6.3V; Temp Range: -55°C to +105°C; Tolerance: 20%; VOLTAGE: 6.3V
D6 = LED: LED GRN SGL 25MA 0603; AGILE_PN: 370-76549; CAD_APPROVED: Yes; HEIGHT: 0.85MM; MFG_NAME01: KINGBRIGHT; MFG_PN01: KPT-1608SGC; ROHS: Yes
D7 = LED: LED ULTRA BRIGHT RED SGL 30MA 0603; AGILE_PN: 370-75079; CAD_APPROVED: Yes; HEIGHT: 0.9MM; MFG_NAME01: LITE ON; MFG_PN01: LTST-C190KRKT; ROHS: Yes; Rated Voltage: 2V; Temp Range: -30° C to + 85° C; Temp_Range: -30° C to + 85° C; VOLTAGE: 2V
J5 = CONN_HDR_2X1: HDR 1X2 TH 100MIL SP 339H AU 98L; 3D_Mechanical_Footprint_File: ftp://fcl.am.freescale.net/ALLEGRO/step/hdr102_95l.STEP; AGILE_PN: 210-81490; CAD_APPROVED: Yes; HEIGHT: 8.59MM; MFG_NAME01: ANYTRONIC CORPORATION LIMITED; MFG_PN01: 0901S0202011N9T-31RF; ROHS: Yes; Temp Range: -55°C to +105°C; Temp_Range: -55°C to +105°C
J135 = CONN_HDR_2X1: HDR 1X2 TH 100MIL SP 339H AU 98L; 3D_Mechanical_Footprint_File: ftp://fcl.am.freescale.net/ALLEGRO/step/hdr102_95l.STEP; AGILE_PN: 210-81490; CAD_APPROVED: Yes; HEIGHT: 8.59MM; Jumper(Default): 1-2; MFG_NAME01: ANYTRONIC CORPORATION LIMITED; MFG_PN01: 0901S0202011N9T-31RF; ROHS: Yes; Temp Range: -55°C to +105°C; Temp_Range: -55°C to +105°C
L2 = INDUCTOR_FERRITE: IND FER BEAD 120 OHM@100MHZ 0.5A 25% 0402; AGILE_PN: 180-77771; CAD_APPROVED: Yes; FPLIST: IND_0402,0402_CC; HEIGHT: 0.55MM; MFG_NAME01: MURATA; MFG_PN01: BLM15AG121SN1D; PART_TYPE: FERRITE\BEAD; Package Size: 0402; ROHS: Yes; Tolerance: 25%
Q5 = 2SK3018: TRANS MOSFET N-CH 30V .1A SOT-323; AGILE_PN: 480-75317; CAD_APPROVED: Yes; HEIGHT: 0.9MM; MFG_NAME01: ROHM; MFG_PN01: 2SK3018T106; ROHS: Yes
Q6 = MOSFET_P: TRAN PMOS PWR 12V 4.3A SOT23; AGILE_PN: 480-77718; CAD_APPROVED: Yes; HEIGHT: 1.12MM; MFG_NAME01: INTERNATIONAL RECTIFIER; MFG_PN01: IRLML6401TRPBF; ROHS: Yes
Q7 Q8 = NPN: TRAN NPN GEN 45V 0.5A SOT-23; AGILE_PN: 480-75158; CAD_APPROVED: Yes; HEIGHT: 1.11 MM; MFG_NAME01: ON SEMICONDUCTOR; ROHS: Yes
R20 = RES: RES MF ZERO OHM 1/16W 5% 0402; AGILE_PN: 470-75394; ASSY_OPT: DNP; CAD_APPROVED: Yes; FPLIST: RC0402_25,RC0402_HD,RC0402_X2,0402_CC; HEIGHT: 0.45 MM; MFG_NAME01: YAGEO AMERICA; MFG_PN01: RC0402JR-070RL; ROHS: Yes; Tolerance: 5%; VOLTAGE: 1/16W
R21 R24 = RES: RES MF 464K 1/10W 1% AEC-Q200 0402; AGILE_PN: 470-31135; CAD_APPROVED: Yes; FPLIST: RC0402_25,RC0402_HD,0402_CC; HEIGHT: 0.40 MM; MFG_NAME01: KOA SPEER; MFG_PN01: RK73H1ETTP4643F; ROHS: Yes; Temp Range: -55C to +155C; Temp_Range: -55C to +155C; Tolerance: 1%; VOLTAGE: 50V
R22 R29 = RES: RES MF ZERO OHM 1/16W 5% 0402; AGILE_PN: 470-75394; CAD_APPROVED: Yes; FPLIST: RC0402_25,RC0402_HD,RC0402_X2,0402_CC; HEIGHT: 0.45 MM; MFG_NAME01: ROHM; MFG_PN01: MCR01MZPJ000; ROHS: Yes; Tolerance: 5%; VOLTAGE: 1/16W
R23 R27 = RES: RES MF 200K 1/10W 1% AEC-Q200 0402; AGILE_PN: 470-31093; CAD_APPROVED: Yes; FPLIST: RC0402_25,RC0402_HD,0402_CC; HEIGHT: 0.40 MM; MFG_NAME01: KOA SPEER; MFG_PN01: RK73H1ETTP2003F; ROHS: Yes; Temp Range: -55C to +155C; Temp_Range: -55C to +155C; Tolerance: 1%
R25 = RES: RES MF 243K 1/10W 1% AEC-Q200 0402; AGILE_PN: 470-31102; CAD_APPROVED: Yes; FPLIST: RC0402_25,RC0402_HD,0402_CC; HEIGHT: 0.40 MM; MFG_NAME01: KOA SPEER; MFG_PN01: RK73H1ETTP2433F; ROHS: Yes; Temp Range: -55C to +155C; Temp_Range: -55C to +155C; Tolerance: 1%
R26 = RES: RES MF 0.02 OHM 1/10W 1% 0603; AGILE_PN: 470-80199; ASSY_OPT: DNP; CAD_APPROVED: Yes; FPLIST: RC0603_OV,RC0603,0603_CC; HEIGHT: 0.457MM; MFG_NAME01: VISHAY INTERTECHNOLOGY; MFG_PN01: WSL0603R0200FEA; ROHS: Yes; TOL: 1%; Tolerance: 1%
R28 R37 = RES: RES MF 100K 1/16W 5% 0402; AGILE_PN: 470-75597; CAD_APPROVED: Yes; FPLIST: RC0402_25,RC0402_HD,0402_CC; HEIGHT: 0.40 MM; MFG_NAME01: VENKEL COMPANY; MFG_PN01: CR0402-16W-104JT; ROHS: Yes; Temp Range: -55C to +155C; Temp_Range: -55C to +155C; Tolerance: 5%; VOLTAGE: 50V
R32 R33 = RES: RES MF 220 OHM 1/10W 5% 0603; AGILE_PN: 470-30297; CAD_APPROVED: Yes; FPLIST: RC0603_OV,RC0603,0603_CC; HEIGHT: 0.6MM; MFG_NAME01: YAGEO AMERICA; MFG_PN01: RC0603JR-07220RL; ROHS: Yes; Tolerance: 5%
R35 R36 = RES: RES MF 2.20K 1/10W 1% 0603; AGILE_PN: 470-75806; CAD_APPROVED: Yes; FPLIST: RC0603_OV,RC0603,0603_CC; HEIGHT: 0.55 MM; MFG_NAME01: BOURNS; MFG_PN01: CR0603-FX-2201ELF; ROHS: Yes; Tolerance: 1%
R38 R39 = RES: RES MF 22K 1/16W 5% 0402; AGILE_PN: 470-75609; CAD_APPROVED: Yes; FPLIST: RC0402_25,RC0402_HD,0402_CC; HEIGHT: 0.41mm; MFG_NAME01: SMEC; MFG_PN01: RC73L2Z223JTF; ROHS: Yes; Tolerance: 5%
R805 R806 = RES: RES MF 1.00k Ohm 1/16W 1% AEC-Q200 0402; AGILE_PN: 470-80511; CAD_APPROVED: Yes; FPLIST: RC0402_25,RC0402_HD,0402_CC; HEIGHT: 0.4 MM; MFG_NAME01: KOA SPEER; MFG_PN01: RK73H1ETTP1001F; ROHS: Yes; Tolerance: 1%
SW2 = EDGE_MOUNT_PB_SW_2: SW SPST PB NO 50MA 12V SMT; AGILE_PN: 510-78253; CAD_APPROVED: Yes; HEIGHT: 5.15MM; MFG_NAME01: WURTH ELEKTRONIK EISOS GMBH & CO. KG (ELECTRONIC & ELECTROMEHANICAL COMP); ROHS: Yes; SILK: ONOFF; Temp Range: -40 to 85 C; Temp_Range: -40 to 85 C
SW3 = EDGE_MOUNT_PB_SW_2: SW SPST PB NO 50MA 12V SMT; AGILE_PN: 510-78253; CAD_APPROVED: Yes; HEIGHT: 5.15MM; MFG_NAME01: WURTH ELEKTRONIK EISOS GMBH & CO. KG (ELECTRONIC & ELECTROMEHANICAL COMP); ROHS: Yes; SILK: POWER RESET; Temp Range: -40 to 85 C; Temp_Range: -40 to 85 C
SW4 = EDGE_MOUNT_PB_SW_2: SW SPST PB NO 50MA 12V SMT; AGILE_PN: 510-78253; CAD_APPROVED: Yes; HEIGHT: 5.15MM; MFG_NAME01: WURTH ELEKTRONIK EISOS GMBH & CO. KG (ELECTRONIC & ELECTROMEHANICAL COMP); ROHS: Yes; SILK: WAKEUP; Temp Range: -40 to 85 C; Temp_Range: -40 to 85 C
SW7 = EDGE_MOUNT_PB_SW_2: SW SPST PB NO 50MA 12V SMT; AGILE_PN: 510-78253; CAD_APPROVED: Yes; HEIGHT: 5.15MM; MFG_NAME01: WURTH ELEKTRONIK EISOS GMBH & CO. KG (ELECTRONIC & ELECTROMEHANICAL COMP); ROHS: Yes; SILK: POR_B RST; Temp Range: -40 to 85 C; Temp_Range: -40 to 85 C
SW8 = EDGE_MOUNT_PB_SW_2: SW SPST PB NO 50MA 12V SMT; AGILE_PN: 510-78253; CAD_APPROVED: Yes; HEIGHT: 5.15MM; MFG_NAME01: WURTH ELEKTRONIK EISOS GMBH & CO. KG (ELECTRONIC & ELECTROMEHANICAL COMP); ROHS: Yes; SILK: GPIO INT BUTTON; Temp Range: -40 to 85 C; Temp_Range: -40 to 85 C
U3 U5 = UM1750S-00_5P: IC VREG LDO ADJ 1-5V 350mA 2.5-6V SOT23-5; AGILE_PN: 315-80554; CAD_APPROVED: Yes; HEIGHT: 1.25MM; MFG_NAME01: UNION SEMICONDUCTOR, INC; ROHS: Yes; VOLTAGE: 2.5-6V
U4 = LM1117_FXD: IC VREG LDO 1.8V 1A  SOT-223; AGILE_PN: 315-82022; CAD_APPROVED: Yes; HEIGHT: 1.8MM; MFG_NAME01: ADVANCED MONOLITHIC SYSTEMS INC; ROHS: Yes; Temp Range: -40 to 125C; Temp_Range: -40 to 125C; VOLTAGE: 1.8V
C528 = CAP_NP: CAP CER 1500PF 50V 10% X7R 0402; AGILE_PN: 150-76273; CAD_APPROVED: Yes; FPLIST: CC0402_25,CC0402_HD,0402_CC; HEIGHT: 0.55MM; MFG_NAME01: AVX; MFG_PN01: 04025C152KAT2A; ROHS: Yes; Tolerance: 10%; VOLTAGE: 50V
D37 = LED_DUAL_SEP_RG: LED RED GRN DUAL 30/25MA SMT; AGILE_PN: 370-75097; CAD_APPROVED: Yes; HEIGHT: 1.1MM; MFG_NAME01: KINGBRIGHT; MFG_PN01: APB3025ESGC-F01
J60 = MICRO_USB_CONN_9PIN: CON 5 USB MICRO-AB RA SKT SMT 0.65MM SP AU; AGILE_PN: 211-78692; CAD_APPROVED: Yes; HEIGHT: 2.8MM; MFG_NAME01: HIROSE; MFG_PN01: ZX62D-AB-5P8(30); ROHS: Yes; SILK: UART TO USB
L29 = IND_FERRITE: IND FER BEAD 120OHM@100MHZ 3A 25% AEC-Q200 0603; AGILE_PN: 180-78352; CAD_APPROVED: Yes; FPLIST: IND_0603,0603_CC; HEIGHT: 0.75MM; MFG_NAME01: MURATA; ROHS: Yes
R900 = RES: RES MF 4.7K 1/16W 5% 0402; AGILE_PN: 470-75626; CAD_APPROVED: Yes; FPLIST: RC0402_25,RC0402_HD,0402_CC; HEIGHT: 0.41mm; MFG_NAME01: NIC COMPONENTS CORP; MFG_PN01: NRCL04J472TRF; ROHS: Yes; Tolerance: 5%
R1327 = RES: RES MF 100 OHM 1/16W 5% 0402; AGILE_PN: 470-75591; CAD_APPROVED: Yes; FPLIST: RC0402_25,RC0402_HD,RC0402_X2,0402_CC; HEIGHT: 0.45mm; MFG_NAME01: NIC COMPONENTS CORP; MFG_PN01: NRCL04J101TRF; ROHS: Yes; Tolerance: 5%
U72 = FT232RQ: IC XCVR USB TO UART CTLR 3.3-5.25V QFN32; AGILE_PN: 312-77380; CAD_APPROVED: Yes; HEIGHT: 1.05MM; MFG_NAME01: FUTURE TECHNOLOGY DEVICES INTERNATIONAL LTD.; ROHS: Yes; VOLTAGE: 3.3/5.25V
U73 = SN74LVC2G126DCTR: IC BUF DUAL TS 1.65-5.5V SSOP8; AGILE_PN: 312-80905; CAD_APPROVED: Yes; HEIGHT: 1.30 MM; MFG_NAME01: TEXAS INSTRUMENTS; ROHS: Yes
U74 = RCLAMP1654P_NEW: DIODE TVS ARRAY 3 5.5V SLP1616P6; AGILE_PN: 480-78843; CAD_APPROVED: Yes; HEIGHT: 0.65MM; MFG_NAME01: SEMTECH CORP; ROHS: Yes; VOLTAGE: 5.5V

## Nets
5V_SDA_PSW: D43.A ; also on sheet 23
5V_SYS: C17.1 C18.1 C25.1 C26.1 J1.2(B1) J1.4(B2) J1.6(B3) J1.8(B4) R7.1 R12.1 U3.1(IN) U3.3(~{SHDN}) U5.1(IN) ; also on sheet 14 19 20 24 25 26 27 29
5V_USB_OTG1: D41.A ; also on sheet 9 19
5V_USB_OTG2: D42.A ; also on sheet 9 19
GND: C1.2 C2.2 C3.2 C5.2 C6.2 C7.2 C8.2 C9.2 C10.2 C11.2 C12.2 C13.2 C14.2 C17.2 C18.2 C19.2 C20.2 C21.2 C22.2 C23.2 C24.2 C25.2 C26.2 C27.2 C28.2 C29.2 C30.2 C31.2 C32.2 C33.2 C399.2 C410.2 C411.2 C412.2 C413.2 C414.2 C466.2 C528.2 C604.2 D1.A(ANODE) D3.4(CATHODE2) H1.1(NC) H2.1(NC) H3.1(NC) H4.1(NC) H5.1(NC) H6.1(NC) J2.2 J2.3 J60.5(GND) Q1.3(G) Q4.2(SOURCE) Q7.2(EMITTER) Q8.2(EMITTER) R11.2 R16.2 R19.2 R23.2 R27.2 R28.2 R30.2 R38.2 R39.2 R805.2 R806.2 R1327.2 SW1.3(NO1) SW1.6(NO2) SW2.1 SW2.3 SW3.1 SW3.3 SW7.1 SW7.3 SW8.1 SW8.3 TP3.1 TP4.1 TP5.1 TP6.1 TVS1.1(A1) U1.4(PGND) U1.6(AGND) U2.1(GND) U3.2(GND) U4.1(GND) U5.2(GND) U72.4(GND1) U72.17(GND2) U72.20(GND4) U72.24(AGND) U72.26(TEST) U72.33(EP) U73.4(GND) U74.7(GND) ; also on sheet 7 8 9 10 11 12 13 14 15 16 17 18 19 20 21 22 23 24 25 26 27 28 29 30 31
VDD_1V8: J4.1 L2.1 ; also on sheet 7 8 9 14 16 21 22 24
VDD_BBSM_3V3: C14.1 R34.1 U2.4(VCC) ; also on sheet 7 22
DBG_OUT_3V3: C411.1 U72.16(3V3OUT)
DBG_RXLED: D37.1(ANODE1) R899.2
DBG_TXLED: D37.3(ANODE2) R898.2
DBUG_5V: C412.1 C413.1 C414.1 L29.1 R898.1 R899.1 R900.1 U72.1(VCCIO) U72.19(VCC)
DBUG_RST: R900.2 U72.18(RESET#)
DBUG_USB_DM: J60.2(D-) U72.15(USBDM) U74.1(DM)
DBUG_USB_DP: J60.3(D+) U72.14(USBDP) U74.2(DP)
DC_5V_IN: C3.1 F1.1 J2.1 R6.1
DCDC_3V3: C8.1 C9.1 J3.2 L1.2 R14.1 TP1.1(TP) U1.5(OUT)
DCDC_3V3_PG: C11.1 C12.1 TP2.1(TP) U1.1(PG) U5.3(~{SHDN})
EWM_OUT_B: C15.1 ; also on sheet 8 22
FLASH_VCC: C399.1 L2.2 R20.2 ; also on sheet 8 11 22
GPIO_BUTTON: C604.1 R2154.2 SW8.2 SW8.4 ; also on sheet 8
LPUART12_RXD: R897.2 TP77.1(TP) U73.6(1Y) ; also on sheet 8 23
LPUART12_TXD: TP78.1(TP) U73.5(2A) ; also on sheet 8 23
NVCC_BBSM: R31.1 R37.1 ; also on sheet 7
NVCC_SD: C27.1 C28.1 R24.1 R25.1 TP7.1(TP) U5.5(OUT) ; also on sheet 8
ONOFF: C31.1 R31.2 SW2.2 SW2.4 ; also on sheet 7
PMIC_ON_REQ: R15.2 ; also on sheet 7
POR_CTL: C32.1 R18.1 R34.2 SW3.2 SW3.4 ; also on sheet 22
RST_TGTMCU_B: C466.1 R1041.2 SW7.2 SW7.4 ; also on sheet 22 26 27
RXD232: U72.2(RXD) U73.3(2Y)
RXLED: D37.2(CATHODE1) U72.21(CBUS1)
SD1_VSELECT: J135.2 ; also on sheet 8
SD_PWREN_B: R29.1 ; also on sheet 8
SENSOR_3V3: C29.1 C410.1 J3.1 Q6.2(SOURCE) R20.1 R22.1 R26.1 R32.1 R33.1 R897.1 R1041.1 R2154.1 U73.8(VCC) ; also on sheet 7 8 9 10 11 12 13 14 15 16 17 18 19 20 21 22 23 24 25 26 27 28 29 30 31
TXD233: U72.30(TXD) U73.2(1A)
TXLED: D37.4(CATHODE2) U72.22(CBUS0)
USB_SUSPEND_B: U72.9(CBUS4) U73.1(1OE) U73.7(2OE)
USER_LED_CTL1: R35.2 ; also on sheet 8
USER_LED_CTL2: R36.2 ; also on sheet 8
VLDO_3V3: C19.1 C20.1 R21.1 U3.5(OUT) ; also on sheet 7
VSD_3V3: C30.1 Q6.3(DRAIN) R26.2 R805.1 R806.1 ; also on sheet 10
WAKEUP: C33.1 SW4.2 SW4.4 ; also on sheet 7
WALL_OV_BASE: Q3.1(B) R5.2
WALL_OV_CTL: D1.C(CATHODE) R3.2 R5.1
WALL_OVP_LED: D2.A Q3.3(C) R10.1
N100054135: Q4.1(GATE) R10.2 R11.1
N100054243: C1.1 C2.1 J1.1(A1) JP1.2 Q2.1(D1) Q2.2(D2) Q2.5(D5) Q2.6(D6) Q2.7(D7) TVS1.2(A2)
N100054253: C4.2 D2.C Q2.3(G) R4.2 R8.1
N100054255: R8.2 R9.1
N100054257: R9.2 SW1.5(COMMON2)
N100054263: F1.2 Q1.1(D1) Q1.2(D2) Q1.5(D5) Q1.6(D6) Q1.7(D7) R1.1 R2.1
N100054299: C4.1 JP1.1 Q1.4(S1) Q1.8(S2) Q2.4(S1) Q2.8(S2) Q3.2(E) R1.2 R2.2 R3.1 R4.1
N100054525: D3.3(ANODE2) R7.2
N100054552: D3.1(ANODE1) R6.2
N100054568: D3.2(CATHODE1) Q4.3(DRAIN)
N100068040: C15.2 D5.C R19.1
N100068056: C10.1 R13.2 R15.1 R17.2 U1.8(EN) U2.2(~{RESET})
N100068060: C13.1 D4.C R18.2
N100068072: C5.1 C6.1 C7.1 R12.2 R13.1 U1.2(VIN)
N100068102: R14.2 R16.1 U1.7(FB)
N100068132: D4.A D5.A R17.1 U2.3(~{MR})
N100208849: C21.1 C22.1 R22.2 U4.3(IN)
N100211328: C23.1 C24.1 J4.2 U4.2(VOUT) U4.4(TAB_VOUT)
N100224476: L1.1 U1.3(SW)
N100310756: J5.1 Q5.1(SOURCE) R24.2 R27.1 U5.4(FB)
N100538770: J135.1 Q5.2(GATE) R28.1
N100538772: J5.2 Q5.3(DRAIN) R25.2
N100979684: R21.2 R23.1 U3.4(FB)
N101069327: R37.2 SW4.1 SW4.3
N101370712: Q6.1(GATE) R29.2 R30.1
N102196396: D6.C(CATHODE) Q7.3(COLLECTOR)
N102196506: Q7.1(BASE) R35.1 R38.1
N102198352: D7.C(CATHODE) Q8.3(COLLECTOR)
N102198373: Q8.1(BASE) R36.1 R39.1
N104653681: J60.1(VBUS) L29.2 U74.6(VBUS)
N104654018: C528.1 J60.6(SHELL1) J60.7(SHELL2) J60.8(SHELL3) J60.9(SHELL4) R1327.1
N104654056: J60.4(ID) U74.3(USB_ID)
N105406651: D41.C J1.3(A2)
N105406660: D42.C J1.5(A3)
N105406670: D43.C J1.7(A4)
N107449906: D6.A(ANODE) R32.2
N107449914: D7.A(ANODE) R33.2

Not connected (* = marked no-connect by the designer): SW1 1(NC1)* 2(COMMON1)* 4(NC2)*; U72 3(RI#)* 5(NC1)* 6(DSR#)* 7(DCD#)* 8(CTS#)* 10(CBUS2)* 11(CBUS3)* 12(NC2)* 13(NC3)* 23(NC6)* 25(NC4)* 27(OSCI)* 28(OSCO)* 29(NC5)* 31(DTR#)* 32(RTS#)*; U74 4(NC1)* 5(NC2)*

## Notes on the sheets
sheet 1
- Resistors and Switch Option List
- PHY0 RMII
- PHY1 RGMII
- PHY2 RGMII
- PHY3 RGMII
- PHY4 RMII
- USE CASE1
- Default setting
- Default  setting
- Default  setting
- Default  setting
- Default setting
- PHY0 MII
- PHY1 RGMII
- PHY2 RGMII
- PHY3 RGMII
- PHY4 MII
- DNP R959, R1229, R1230. R1122,
  R1235, R1233, R1234, R1240, R1239,
  R1237, R1238, R405, R1236
- DNP R1289, R1292, R1290, R1291,
  R1293, R1294, R1295, R1296, R1288, R1313
- USE CASE2
- Default  setting
- Default  setting
- Default  setting
- Populate R960, R1231, R1232, R1259,
  R1260, R1261, R1262, R1263, R1264,
  R1265, R1266, R1267, R1268, R1269,
  R1270, R1271, R1272, R1273, R1274
- Populate R1297 R1298, R1299, R1300, R1302,
  R1301, R1303, R1304, R1305, R1307, R1306,
  R1308, R1310, R1309, R1311, R1312, R2116,
  R2117, R2120,R2121, R2124, R2125, R2128,
  R2129, R2132, R2133, R1169
- U96, U97, U98, U99, U100 and U101
  Switch to signal path B
- U103, U106 Switch to signal path B
sheet 2
- Serial12 To USB
- USB Device Only
- GPIOs
  200K PU to VCCIO
  Vin Switch pt - 1.0 to 1.5V
  for all Vccs
- {VCCIO 1.8V-5.25V}
- {VCC 4.0V-5.25V}
- {5V logic level}
- {5V logic level}
- {50mOhms DC @2A}
- Level-Shifter to
  insure no IO backfeed
sheet 3
- MIMXRT1180-EVK
- Table of Content
- Revision History
- Page 1
- Cover
- Rev. Code
- Date
- By
- Description
- Page 2
- Block Diagram
- Page 3
- Main Power
- X1
- 2021-07-06
- Shawn Shi
- Draft version
- Page 4
- Power Domain
- A
- 2021-11-15
- Shawn Shi
- Initial Release
- Page 5
- MIMXRT1180 Part1
- 1. Add  one more GPIO intterrupt button.
  2. Re-assign CANx_TX/CANx_RX to IOMUX without Boot mode config function.
  3. Consolidate MDC/MDIO of all 5 ethernet PHY using the same pinout.
  4. Add dedicate buffer for all system reset logic control.
  5. Replace audio codec chip WM8960(To be EOL) with WM8962.
  6. Replace OCT Flash from MX25UM51345GXDI00 to MT35XU512ABA2G12-0AAT.
- Page 6
- MIMXRT1180 Part2
- B
- 2022-03-18
- Shawn Shi
- Page 7
- MIMXRT1180 Part3
- Page 8
- SD Card
- 1. Changed HyperRAM from S27KL0642DPBHB020 to W957A8MFYA5K.
  2. Changed ADC VREF external option to VDD_1V8.
  3. Remove route of MCULINK TRG_RST to MCU JTAG_nTRST.
  4. Change ENET2&ENET3 signals to be enabled, so 5 ENET are avaible as default.
  5. Change HyperRAM to be enabled and disable SDRAM by default.
  6. Change ENET1_INT_B,ENET1_RST_B to 1V8 pullup.
  7. Enable the ISP Automatic Control using jumper setting instead of 0ohm resitors.
  8. Add jumper J105 for WIFI_WAKE_B_3V3 signal, default open.
  9. Populate R782, R783 and R778.
- Page 9
- FLEXSPI Flash
- C
- 2023-03-17
- Shawn Shi
- Page 10
- LPSPI Flash
- Page 11
- SDRAM_opt/HyperRAM
- Page 12
- DMIC
- Page 13
- SAI
- 1. Reserve 1pc RGMII/RMII connector for PHY daughter card extension.
  2. Reserve LPSPI option to enable new radio features/functionality.
  3. Replace EEprom with 24LC32A.
- C1
- 2023-05-05
- Shawn Shi
- Page 14
- SPDIF
- Page 15
- PHY0_RMII/MII_ECAT0
- 1. Add level shifter for  ENET1_INT_B/ENET3_INT_B,ENET1_RST_B/ENET3_RST_B.
  2. Correct PN from  MIMXRT1189CVM8A to  MIMXRT1189CVM8B.
  3. Assign SD1_VSELECT to GPIO_AD_34.
  4. Change DECAP over VDDA_1P8_IN to 1uF.
- C2
- 2023-06-20
- Shawn Shi
- Page 16
- PHY1_RGMII
- Page 17
- PHY2_RGMII
- No layout change
  1. Replace HyperRAM with W956A8MBYA5K.
  2. Replace SINC ADC with AMC1106M05DWV.
  3. DNP R142 for ECAT_LINK.
  4. Change JP7 default setting to OPEN.
- Page 18
- PHY3_RGMII
- C3
- 2023-10-11
- Shawn Shi
- Page 19
- PHY4_RMII/MII_ECAT1
- Page 20
- RGMII/MII/RMII DC
- Page 21
- USB
- C4
- 2025-02-28
- Shawn Shi
- 1. Change RT1180 silicon from MIMXRT1189CVM8B to MIMXRT1189CVM8C.
  2. Add notes on Page15 & Page19, No POE function supported.
- Page 22
- CAN
- Page 23
- M.2 Socket
- Page 24
- Boot
- Page 25
- MCU-Link
- Page 26
- Interface/JTAG
- Jumper Setting
- Switch Setting
- Page 27
- Audio Extension
- Page 28
- SINC&I3C
- REF DES
- JUMPER(DEFAULT)
- PAGE NAME
- REF DES
- SWITCH(DEFAULT)
- PAGE NAME
- J1,J3
- 1-2
- 03 Main Power
- SW5
- off,off.off,on
- 24 Boot
- Page 29
- Serial to USB
- J4,J135
- 1-2
- 04 Power Domain
- J6,J9,J12,J14,J77
- 1-2
- 05 MIMXRT1180 Part1
- Page 30
- MISC
- J11
- 2-3
- 05 MIMXRT1180 Part1
- J76
- 1-2
- 08 SD Card
- Page 31
- Use Case Description
- J57
- 2-3
- 08 SD Card
- J58,J59,J75
- 2-3
- 09 FLEXSPI Flash
- J97,J98,J99,J100
- 1-2
- 13 SAI
- J65,J72
- 2-3
- 17 PHY2_RGMII
- J63,J73
- 2-3
- 18 PHY3_RGMII
- J78,J79
- 1-2
- 23 M.2 Socket
- J90,J91,J93
- 1-2
- 24 Boot
- JP6
- 1-2
- 25 MCU-Link
- 3. Device type number is for reference only. The number
  varies with the manufacturer.
- 1. Unless Otherwise Specified:
- All resistors are in ohms, 1/16 Watt,0402
- 4. Special signal usage:
- All capacitors are in uF,0402
- _B Denotes - Active-Low Signal
- All voltages are DC
- <> or [] Denotes - Vectored Signals
- All polarized capacitors are aluminum electrolytic
- 5. Interpret diagram in accordance with American
  National Standards Institute specifications, current
  revision, with the exception of logic block symbology.
- 2. Interrupted lines coded with the same letter or letter
      combinations are electrically connected.
sheet 4
- MIMXRT1180-EVK
- #####  Block Diagram RevC4 #####
- PHYx2 (MII/RMII)
- PHYx3 (RGMII)
- CAN x2
- ENET CONx1(opt)
- USB OTG1
- USB OTG2
- 10/100 Mbps
  RTL8201FI
- 10/100/1000 Mbps
  RTL8211FDI-CG
- Button/LED
- TJA1057GT/3
- For PHY DC
- MII/RMII/RGMII
- USB OTG1
- USB OTG2
- CANFD
- MII/RMII
- RGMII
- I/O
- OCT Flash
- MT35XU512ABA2G12-0AAT
- QSPI Flash
- FlexSPI
- POWER
- FlexSPI
- POWER
- W25Q128JWSIQ
- HyperRAM
- W956A8MBYA5K
- NXP
   MIMXRT1189CVM8C
- SEMC
- SDRAM 16bit * 2
- WIFI/BLE
- SDIO/UART/I2S
- SEMC
- SDHC/UART/I2S
- 256Mb:W9825G6KH-5I
- M.2 CON
- (Disabled by default)
- SD0
- SD SLOT
- I2C/GPIO/I2S
- SDHC
- Audio CON
- I2C/GPIO/I2S
- T-Flash
- Extension
- I2C/INT/I3C
- CLK/DATA
- I2S
- SPDIF
- SINC
- LPSPI/I2C
- Arduino/FLEXIO
- JTAG/MCULINK
- MX25L4006
- Motion Sensors
- ARDUINO
   FLEXIO
- DMIC x 4
- CODEC
- SPDIF
- SINC ADC
- LPSPI Flash
- JTAG/MCULINK
- FXLS8974CFR3
- 24LC32A
- GYRO LSM6DSOXTR
- 8CH Extension
- Wolfson WM8962
- PIN Header
- PIN Header
- IN/OUT
- AMC1106
- EEPROM for ECAT
- HP
- MIC
sheet 5
- Main Power
- Reverse Voltage Protection
- Over-Voltage Protection
- Barrel Connector
- Default:1-2
- SW1(2-3/5-6) ->5V ON
  SW1(1-2/4-5) ->5V OFF
- 5V To 3.3V For Whole System
- Current 3A
  I_Quiescent : 40μA
- ISAT=4.85A
- 5V
- Vfb=0.6V
- Default: 1-2
- # R36/R39 = 4.5
- # PG pin is pulled up to
  VIN by the internal
  resistor 500K OHM
- # GPIO/WDOG PWR OFF->ON
- Ground TPs
- Board Mounting Holes
- Layout Note: Place Ground TPs
  to assist signal measurement.
sheet 6
- 3V3 LDO for BBSM
- 1V8 LDO
- MAX 350mA
- MAX 1A
- Vfb=1V
- Flash VCC Option
  1.8V default
- Default: 1-2
- NVCC_SD <SD3.0>
- SD Card Power Switch
- MAX 350 mA
- Default:Open
- Vfb=1V
- # 1.8V/3.3V
- # Default: 3.3V
- Default:1-2
- Buttons
- USER LED1
- USER LED2
- # CPU ONOFF Button
- # System Reset Button
- # POR_B Pin RESET Button
- # GPIO Interrupt Button
- # CPU Wakeup Button
